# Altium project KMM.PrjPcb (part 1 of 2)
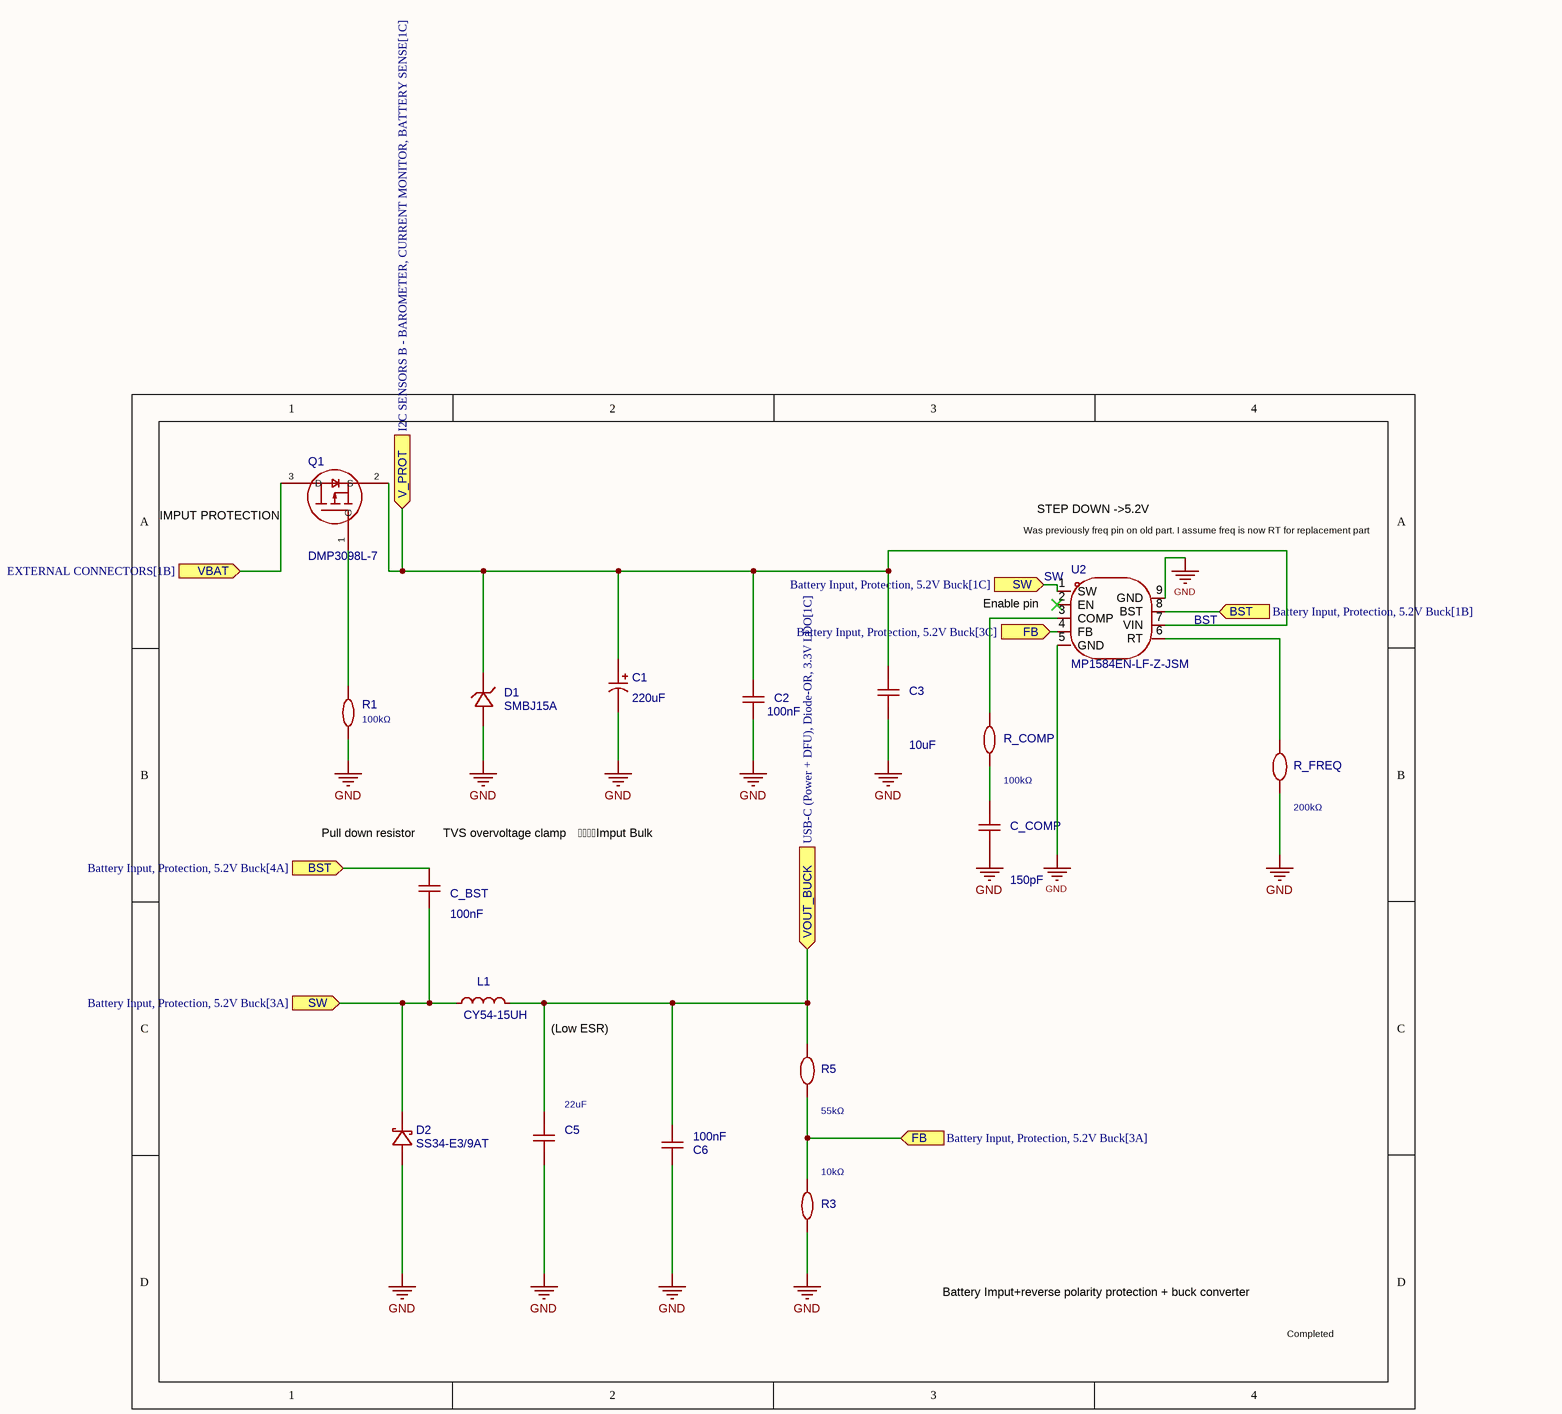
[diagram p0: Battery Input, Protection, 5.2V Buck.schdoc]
8 sheets, 81 parts. Net scope: flat (ports and power ports of the same name join across sheets).
Board file: PCB1.PcbDoc
Sheets:
  Battery Input, Protection, 5.2V Buck.schdoc
  EXTERNAL CONNECTORS.schdoc
  I2C Sensors A- IMU and Magnetometer.schdoc
  I2C SENSORS B - BAROMETER, CURRENT MONITOR, BATTERY SENSE.schdoc
  MCU Support Circuit.schdoc
  RC INPUT, STATUS LED, SWD HEADER.schdoc
  STM32F446RET6 Core.schdoc
  USB-C (Power + DFU), Diode-OR, 3.3V LDO.schdoc

## Sheet Battery Input, Protection, 5.2V Buck.schdoc
size 241 x 190 mm; Device: Altium_A; SheetNumber: 1; SheetTotal: 8; Name: Altium_A; Width: 950; Height: 750; X Region Count: 4; Y Region Count: 4; Blade Width: 20; Region Start: 1; Border: 1; Title Block Position: 3

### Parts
C1  220uF  [CAP-SMD_BD8.0-L8.3-W8.3-LS9.1-FD]
C2  100nF  [0603C]
C3  10uF  [0603C]
C5  22uF  [0603C]
C6  100nF  [0603C]
C_BST  100nF  [0603C]
C_COMP  150pF  [0603C]
D1  SMBJ15A  [SMB_L4.6-W3.5-LS5.3-RD]
D2  SS34-E3/9AT  [SMC-2_7r94x5r91-H2r34_C]
L1  CY54-15UH  [IND-SMD_L5.8-W5.2]
Q1  DMP3098L-7  [SOT-23_L2.9-W1.3-P1.90-LS2.4-BR]
R1  100kΩ  [0805R]
R3  10kΩ  [0805R]
R5  55kΩ  [0603R]
R_COMP  100kΩ  [0805R]
R_FREQ  200kΩ  [0603R]
U2  MP1584EN-LF-Z-JSM  [ESOP-8_L4.9-W3.9-P1.27-LS6.0-BL-EP-2]

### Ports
BST (in, see Battery Input, Protection, 5.2V Buck[1B]), BST (in, see Battery Input, Protection, 5.2V Buck[4A]), FB (in, see Battery Input, Protection, 5.2V Buck[3A]), FB (in, see Battery Input, Protection, 5.2V Buck[3C]), SW (in, see Battery Input, Protection, 5.2V Buck[1C]), SW (in, see Battery Input, Protection, 5.2V Buck[3A]), V_PROT (in, see I2C SENSORS B - BAROMETER, CURRENT MONITOR, BATTERY SENSE[1C]), VBAT (in, see EXTERNAL CONNECTORS[1B]), VOUT_BUCK (in, see USB-C (Power + DFU), Diode-OR, 3.3V LDO[1C])

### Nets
GND: C1.2 C2.2 C3.2 C5.2 C6.2 C_COMP.2 D1.2(A) D2.2(A) R1.2 R3.2 R_FREQ.2 U2.5(GND) U2.9(GND)
BST: C_BST.1 U2.8(BST) ; port BST
SW: C_BST.2 D2.1(K) L1.1 U2.1(SW) ; port SW
NetC1_1: C1.1 C2.1 C3.1 D1.1(C) Q1.2(S) U2.7(VIN) ; port V_PROT
NetC5_1: C5.1 C6.1 L1.2 R5.1 ; port VOUT_BUCK
NetC_COMP_1: C_COMP.1 R_COMP.2
NetJ_BAT_1: Q1.3(D) ; port VBAT
NetQ1_1: Q1.1(G) R1.1
NetR3_1: R3.1 R5.2 U2.4(FB) ; port FB
NetR_COMP_1: R_COMP.1 U2.3(COMP)
NetR_FREQ_1: R_FREQ.1 U2.6(RT)

Not connected (* = marked no-connect by the designer): U2 2(EN)*

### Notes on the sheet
- (near Q1) IMPUT PROTECTION
- Was previously freq pin on old part. I assume freq is now RT for replacement part
- STEP DOWN ->5.2V
- (near U2) Enable pin
- (near C_BST) Pull down resistor
- (near C_BST) TVS overvoltage clamp
- Imput Bulk
- (near L1) (Low ESR)
- Battery Imput+reverse polarity protection + buck converter
- Completed

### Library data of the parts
C1 = RVT1V221M0810 220UF 35V: Capacitance:220uF Tolerance:±20% Tolerance:±20% Voltage Rating:35V Ripple Current:195mA@120Hz Equivalent Series Resistance(ESR):- Diameter:8mm Height - Seated (Max):10.2mm Lifetime:2800hrs@105℃ Operating Temperature:-55℃~+105℃ Operating Temperature:-55℃~+; Manufacturer: DMBJ(振宝佳); Add into BOM: yes; Tolerance: ±20%; Voltage Rating: 35V; 3D Model: 9f9fc6857dc54a0ab164c419dde4584d; 3D Model Transform: 358.267,326.771,0,0,0,0,0,0,0
C2 C6 C_BST = CT41G-0603-2X1-50V-0.1uF-K(N): Capacitance:100nF Tolerance:±10% Tolerance:±10% Voltage Rating:50V Temperature Coefficient:-; Manufacturer: TORCH(火炬); Symbol: CT41G-0603-2X1-50V-0.1μF-K(N); Add into BOM: yes; Tolerance: ±10%; Voltage Rating: 50V; 3D Model: 624118aa3cc7497086c383c2d72e0852; 3D Model Transform: 62.992,31.496,0,0,0,0,0,0,0; ModelName: C0603_L1.6-W0.8-H0.8
C3 = 0603X106M250NT: Capacitance:10uF Tolerance:±20% Tolerance:±20% Voltage Rating:25V Temperature Coefficient:X5R; Manufacturer: FH(风华); Tolerance: ±20%; Voltage Rating: 25V; Add into BOM: yes; 3D Model: 624118aa3cc7497086c383c2d72e0852; 3D Model Transform: 62.992,31.496,0,0,0,0,0,0,0; Temperature Coefficient: X5R; ModelName: C0603_L1.6-W0.8-H0.8
C5 = CC0603MRX6S5BB226: Capacitance:22uF Tolerance:±20% Tolerance:±20% Voltage Rating:6.3V Temperature Coefficient:X6S; Manufacturer: YAGEO(国巨); Tolerance: ±20%; Voltage Rating: 6.3V; Add into BOM: yes; 3D Model: 624118aa3cc7497086c383c2d72e0852; 3D Model Transform: 62.992,31.496,0,0,0,0,0,0,0; Temperature Coefficient: X6S; ModelName: C0603_L1.6-W0.8-H0.8
C_COMP = CC0603CG50V151JN: Capacitance:150pF Tolerance:±5% Tolerance:±5% Voltage Rating:50V Temperature Coefficient:; Manufacturer: TORCH(火炬); Tolerance: ±5%; Voltage Rating: 50V; Add into BOM: yes; 3D Model: 624118aa3cc7497086c383c2d72e0852; 3D Model Transform: 62.992,31.496,0,0,0,0,0,0,0; ModelName: C0603_L1.6-W0.8-H0.8
D1 = SMBJ15A_C2912077: Polarity:Unidirectional Reverse Stand-Off Voltage (Vrwm):15V Clamping Voltage:24.4V Peak Pulse Current (Ipp):24.6A Peak Pulse Power Dissipation (Ppp):600W Voltage - Breakdown:18.5V Reverse Leakage Current (Ir):1uA Number of Channels:1 Operating Temperatur; Manufacturer: LRC(乐山无线电); Number of Channels: 1; Clamping Voltage: 24.4V; Add into BOM: yes; 3D Model: a9030ce42b7146a0b12fc063e3812f30; 3D Model Transform: 208.661,139.764,0,0,0,0,0,0,0; Reverse Stand-Off Voltage (Vrwm): 15V; Peak Pulse Current (Ipp): 24.6A; Peak Pulse Power Dissipation (Ppp): 600W; Voltage - Breakdown: 18.5V; Reverse Leakage Current (Ir): 1uA; Type: TVS
D2 = SS34-E3/9AT: Diode Configuration:1 Independent Voltage - Forward(Vf@If):500mV@3A Voltage - DC Reverse(Vr):40V Current - Rectified:3A Reverse Leakage Current (Ir):500uA@40V Operating Junction Temperature Range:-55℃~+150℃ Operating Junction Temperature Range:-55℃~+150℃; Manufacturer: VISHAY(威世); Add into BOM: yes; 3D Model: 181deed3e51b4528a83dd624c23bafda; 3D Model Transform: 314.96,236.22,0,0,0,0,0,0,0; Voltage - DC Reverse(Vr): 40V; Current - Rectified: 3A; Non-Repetitive Peak Forward Surge Current: 100A; ModelName: SMC_L6.9-W5.9-LS7.9-RD
L1 = CY54-15UH: Manufacturer: SHOU HAN(首韩); Add into BOM: yes; 3D Model: 65134515052944169492d54da43c5ebb; 3D Model Transform: 204.724,223.43,0,90,0,0,0,-0.018,0; ModelName: IND-SMD_L5.8-W5.2-H4.5
Q1 = DMP3098L-7: Number:1 P-Channel Drain to Source Voltage:30V Current - Continuous Drain(Id):3.8A RDS(on):120mΩ@4.5V Pd - Power Dissipation:1.08W Gate Threshold Voltage (Vgs(th)):2.1V Gate Charge(Qg):8nC@4.5V Input Capacitance(Ciss):336pF Reverse Transfer Capacitance (C; Manufacturer: DIODES(美台); Add into BOM: yes; 3D Model: 62a57c6760504a01965db6419a6d07df; 3D Model Transform: 98.64468,114.173,0,180,0,0,0.001,-0.002,0; Drain to Source Voltage: 30V; Current - Continuous Drain(Id): 3.8A; Pd - Power Dissipation: 1.08W; Gate Threshold Voltage (Vgs(th)): 2.1V; Input Capacitance(Ciss): 336pF; Reverse Transfer Capacitance (Crss@Vds): 147pF; Output Capacitance(Coss): 210pF; Vgs: ±20V; ModelName: SOT-23-3P_L2.9-W1.3-H1.0-LS2.4-P0.95
R1 = CR0805J80104G: Type:Thick Film Resistors Resistance: Tolerance:±5% Tolerance:±5% Power(Watts): Overload Voltage (Max): Temperature Coefficient:±200ppm/℃ Temperature Coefficient:±200ppm/℃ Operating Temperature Range:-55℃~+125℃ Operating Temperature Range:-55℃~+125℃; Manufacturer: LIZ(丽智电子); Add into BOM: yes; Tolerance: ±5%; 3D Model: b83c7c5430874b8eb2319a65d9433429; 3D Model Transform: 78.74,51.181,0,0,0,0,0,-0.0005,0; ModelName: R0805_L2.0-W1.3-H0.6
R3 = 0805W8F1002T5E: Type:Thick Film Resistor Resistance:10kΩ Tolerance:±1% Tolerance:±1% Power(Watts):125mW Voltage-Supply(Max):150V Temperature Coefficient:±100ppm/℃ Temperature Coefficient:±100ppm/℃ Operating Temperature:-55℃~+155℃ Operating Temperature:-55℃~+155℃; Manufacturer: UNI-ROYAL(厚声); Add into BOM: yes; Tolerance: ±1%; 3D Model: b83c7c5430874b8eb2319a65d9433429; 3D Model Transform: 78.74,51.181,0,0,0,0,0,-0.0005,0; Power(Watts): 125mW; Voltage-Supply(Max): 150V; ModelName: R0805_L2.0-W1.3-H0.6
R5 = CR165502F: Type:Thick Film Resistor Resistance:55kΩ Tolerance:±1% Tolerance:±1% Power(Watts):100mW Temperature Coefficient:±100ppm/℃ Temperature Coefficient:±100ppm/℃ Operating Temperature:-55℃~+155℃ Operating Temperature:-55℃~+155℃; Manufacturer: Meritek; Add into BOM: yes; Tolerance: ±1%; 3D Model: 112863783b5b41f1b5254f87eedc7932; 3D Model Transform: 31.8897,63.7794,0,90,0,0,0,0,0; Power(Watts): 100mW; ModelName: R0603
R_COMP = CR0805J80104G: Type:Thick Film Resistors Resistance: Tolerance:±5% Tolerance:±5% Power(Watts): Overload Voltage (Max): Temperature Coefficient:±200ppm/℃ Temperature Coefficient:±200ppm/℃ Operating Temperature Range:-55℃~+125℃ Operating Temperature Range:-55℃~+125℃; Manufacturer: LIZ(丽智电子); Tolerance: ±5%; Add into BOM: yes; 3D Model: b83c7c5430874b8eb2319a65d9433429; 3D Model Transform: 78.74,51.181,0,0,0,0,0,-0.0005,0; ModelName: R0805_L2.0-W1.3-H0.6
R_FREQ = FRC0603F2003TS: Type:Thick Film Resistor Resistance:200kΩ Tolerance:±1% Tolerance:±1% Power(Watts):100mW Voltage-Supply(Max):75V Temperature Coefficient:±100ppm/℃ Temperature Coefficient:±100ppm/℃ Operating Temperature:-55℃~+155℃ Operating Temperature:-55℃~+155℃; Manufacturer: FOJAN(富捷); Add into BOM: yes; Tolerance: ±1%; 3D Model: 112863783b5b41f1b5254f87eedc7932; 3D Model Transform: 31.8897,63.7794,0,90,0,0,0,0,0; Power(Watts): 100mW; Voltage-Supply(Max): 75V; ModelName: R0603
U2 = MP1584EN-LF-Z-JSM: Function:Step-down type Voltage - Supply:4.5V~40V Voltage - Supply:4.5V~40V Output Voltage:800mV~37V Output Voltage:800mV~37V Output Current:3A Frequency - Switching:100kHz~220kHz Frequency - Switching:100kHz~220kHz Operating Temperature:-40℃~+125℃ Operat; Manufacturer: JSMSEMI(杰盛微); Output Type: Adjustable; Output Current: 3A; Add into BOM: yes; 3D Model: e5df7a25454141cab5fb3454c06ecccd; 3D Model Transform: 192.913,236.22,0,0,0,0,0,0,0; Synchronous Rectifier: No; Number of Outputs: 1; Topology: Buck; Quiescent Current: 65uA; Switch tube (built-in/external): Built-in

## Sheet EXTERNAL CONNECTORS.schdoc
size 241 x 190 mm; Device: Altium_A; SheetNumber: 2; SheetTotal: 8; Name: Altium_A; Width: 950; Height: 750; X Region Count: 4; Y Region Count: 4; Blade Width: 20; Region Start: 1; Border: 1; Title Block Position: 3
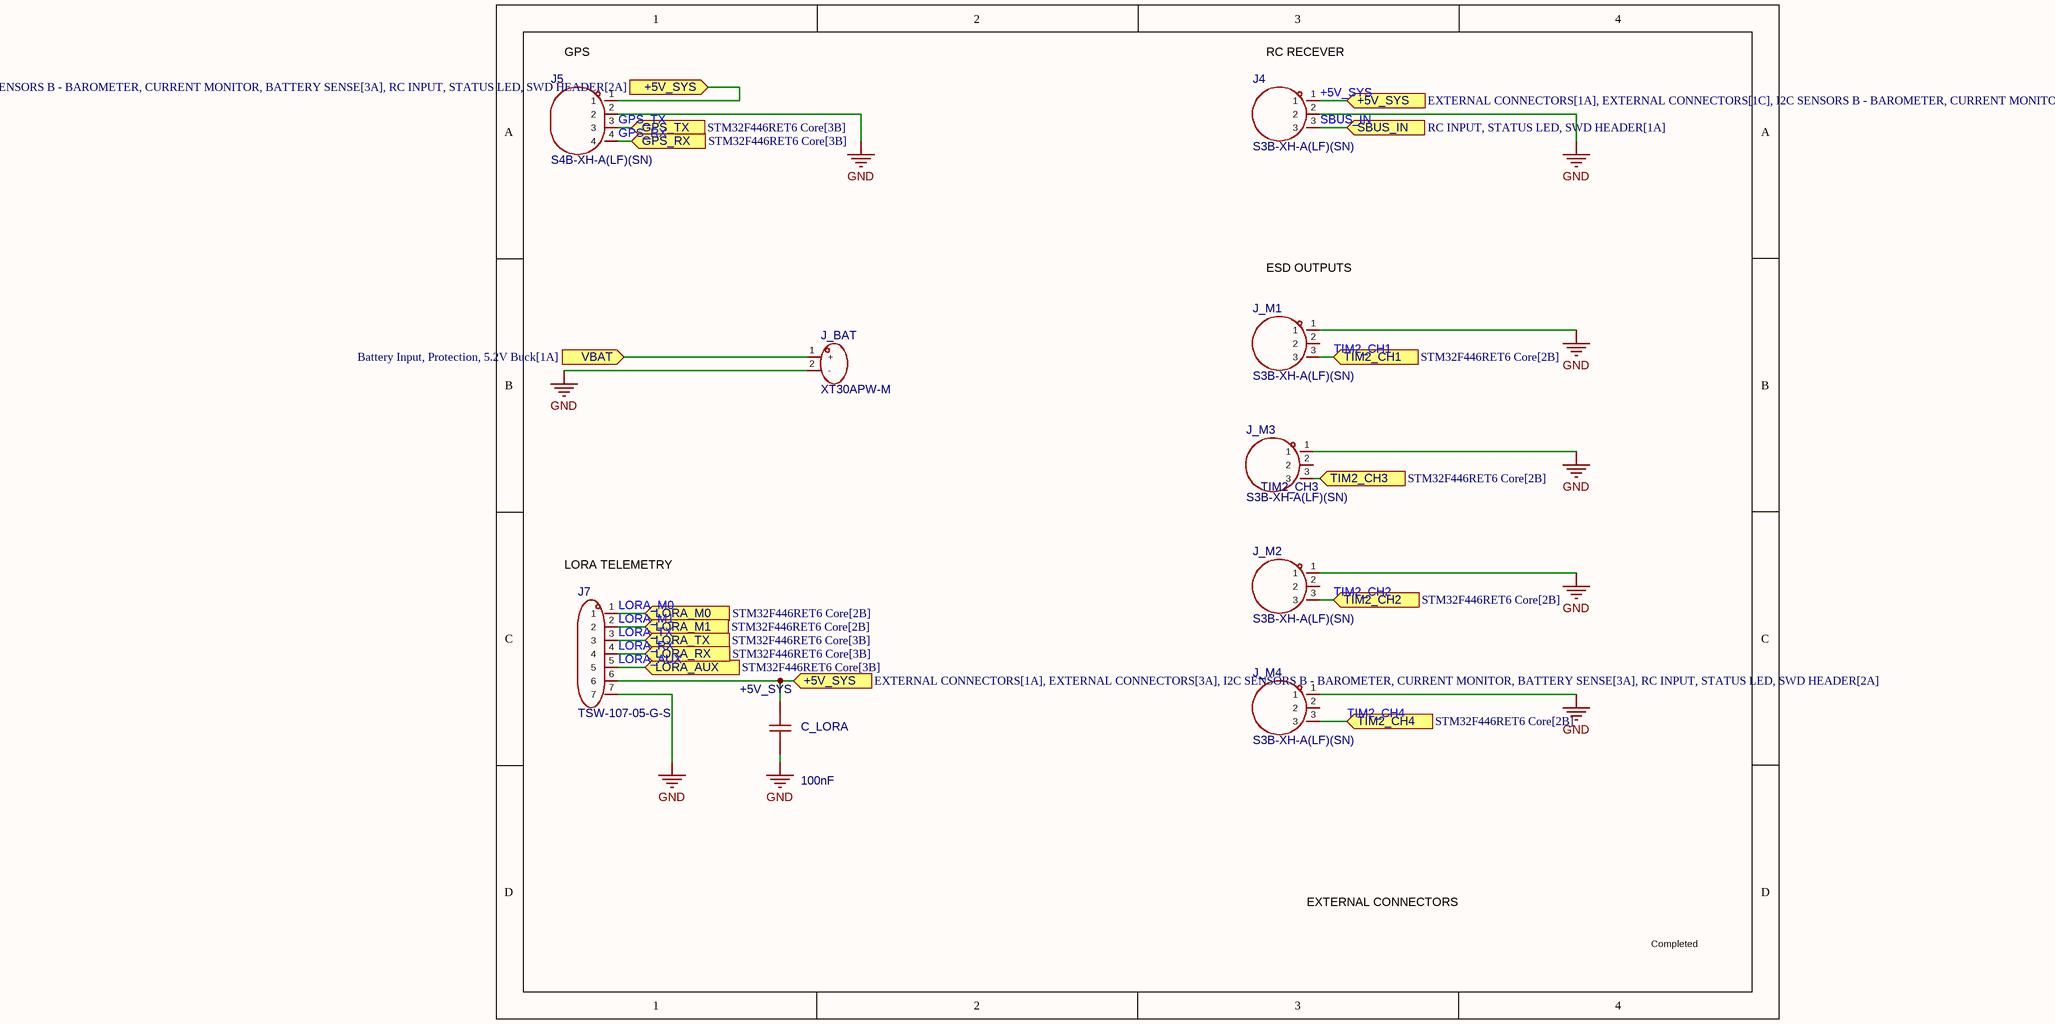
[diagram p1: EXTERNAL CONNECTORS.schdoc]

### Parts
C_LORA  100nF  [0603C]
J4  S3B-XH-A(LF)(SN)  [CONN-TH_S3B-XH-A-LF-SN]
J5  S4B-XH-A(LF)(SN)  [CONN-TH_S4B-XH-A-LF-SN]
J7  TSW-107-05-G-S  [HDR-TH_7P-P2.54-V-M]
J_BAT  XT30APW-M  [CONN-TH_XT30APW-M]
J_M1  S3B-XH-A(LF)(SN)  [CONN-TH_S3B-XH-A-LF-SN]
J_M2  S3B-XH-A(LF)(SN)  [CONN-TH_S3B-XH-A-LF-SN]
J_M3  S3B-XH-A(LF)(SN)  [CONN-TH_S3B-XH-A-LF-SN]
J_M4  S3B-XH-A(LF)(SN)  [CONN-TH_S3B-XH-A-LF-SN]

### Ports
+5V_SYS (in, see EXTERNAL CONNECTORS[1A], EXTERNAL CONNECTORS[1C], I2C SENSORS B - BAROMETER, CURRENT MONITOR, BATTERY SENSE[3A], RC INPUT, STATUS LED, SWD HEADER[2A]), +5V_SYS (in, see EXTERNAL CONNECTORS[1A], EXTERNAL CONNECTORS[3A], I2C SENSORS B - BAROMETER, CURRENT MONITOR, BATTERY SENSE[3A], RC INPUT, STATUS LED, SWD HEADER[2A]), +5V_SYS (in, see EXTERNAL CONNECTORS[1C], EXTERNAL CONNECTORS[3A], I2C SENSORS B - BAROMETER, CURRENT MONITOR, BATTERY SENSE[3A], RC INPUT, STATUS LED, SWD HEADER[2A]), GPS_RX (in, see STM32F446RET6 Core[3B]), GPS_TX (in, see STM32F446RET6 Core[3B]), LORA_AUX (in, see STM32F446RET6 Core[3B]), LORA_M0 (in, see STM32F446RET6 Core[2B]), LORA_M1 (in, see STM32F446RET6 Core[2B]), LORA_RX (in, see STM32F446RET6 Core[3B]), LORA_TX (in, see STM32F446RET6 Core[3B]), SBUS_IN (in, see RC INPUT, STATUS LED, SWD HEADER[1A]), TIM2_CH1 (in, see STM32F446RET6 Core[2B]), TIM2_CH2 (in, see STM32F446RET6 Core[2B]), TIM2_CH3 (in, see STM32F446RET6 Core[2B]), TIM2_CH4 (in, see STM32F446RET6 Core[2B]), VBAT (in, see Battery Input, Protection, 5.2V Buck[1A])

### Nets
GND: C_LORA.2 J4.2 J5.2 J7.7 J_BAT.2(-) J_M1.1 J_M2.1 J_M3.1 J_M4.1
+5V_SYS: C_LORA.1 J4.1 J5.1 J7.6 ; port +5V_SYS
GPS_RX: J5.4 ; port GPS_RX
GPS_TX: J5.3 ; port GPS_TX
LORA_AUX: J7.5 ; port LORA_AUX
LORA_M0: J7.1 ; port LORA_M0
LORA_M1: J7.2 ; port LORA_M1
LORA_RX: J7.4 ; port LORA_RX
LORA_TX: J7.3 ; port LORA_TX
SBUS_IN: J4.3 ; port SBUS_IN
TIM2_CH1: J_M1.3 ; port TIM2_CH1
TIM2_CH2: J_M2.3 ; port TIM2_CH2
TIM2_CH3: J_M3.3 ; port TIM2_CH3
TIM2_CH4: J_M4.3 ; port TIM2_CH4
NetJ_BAT_1: J_BAT.1(+) ; port VBAT

Not connected (* = marked no-connect by the designer): J_M1 2; J_M2 2; J_M3 2; J_M4 2

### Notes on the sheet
- (near J5) GPS
- (near J4) RC RECEVER
- ESD OUTPUTS
- (near J7) LORA TELEMETRY
- EXTERNAL CONNECTORS
- Completed

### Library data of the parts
C_LORA = 06035C104K4T2A: Capacitance:100nF Tolerance:±10% Tolerance:±10% Voltage Rating:50V Temperature Coefficient:X7R; Manufacturer: Kyocera AVX; Add into BOM: yes; Tolerance: ±10%; Voltage Rating: 50V; 3D Model: 624118aa3cc7497086c383c2d72e0852; 3D Model Transform: 62.992,31.496,0,0,0,0,0,0,0; Temperature Coefficient: X7R; ModelName: C0603_L1.6-W0.8-H0.8
J4 J_M1-J_M4 = S3B-XH-A(LF)(SN): Pins Structure:1x3P Pitch:2.5mm Mounting Style:Bend insert Reference Series:XH Number of Pins:3P Number of Rows:1 Number of PINs Per Row:3 Row Spacing:- Current Rating (Max):3A Contact Material:Brass Contact Plating:Tin Operating Temperature Range:-25℃~+8; Manufacturer: JST; Add into BOM: yes; 3D Model: 53e830ec92554ce8b6ebb98afce921f9; 3D Model Transform: 389.763,452.755,0,0,0,0,0,136.378,-137.795; Pins Structure: 1x3P; Pitch: 2.5mm; Reference Series: XH; Number of PINs Per Row: 3; Current Rating (Max): 3A; Rated Voltage (Max): 250V; Plastic Material: PA66; Flame Retardant Rating: UL94V-0; Supplementary Features: K-leg punch; Z-Height of the Board: 6.1mm; X-Length of Bottom Edge on Board (Spacing Line): 9.9mm; Y-Width of Bottom Edge on Board: 11.5mm
J5 = S4B-XH-A(LF)(SN): Pins Structure:1x4P Pitch:2.5mm Mounting Type:Right Angle Reference Series:XH Number of Pins:4P Number of Rows:1 Number of PINs Per Row:4 Row Spacing:- Current Rating:3A Contact Material:Brass Contact Plating:Tin Operating Temperature:-25℃~+85℃ Operating; Manufacturer: JST; Add into BOM: yes; Voltage Rating: 250V; 3D Model: 77a2ced4cba941c49e3f4130b9ad2f4f; 3D Model Transform: 488.19194,452.755,0,180,0,0,0.591,136.378,-133.858; Pins Structure: 1x4P; Pitch: 2.5mm; Reference Series: XH; Number of PINs Per Row: 4; Current Rating: 3A; Plastic Material: PA66; Flame Retardant Rating: UL94V-0; Supplementary Features: K Pin; Z-Height of the Board: 6.1mm; X-Length of Bottom Edge on Board (Spacing Line): 12.4mm; Y-Width of Bottom Edge on Board: 11.5mm
J7 = TSW-107-05-G-S: Pitch:2.54mm Mounting Type:Through Hole Number of Rows:1 Number of Pins:7P Contact Material:Phosphor Bronze Contact Plating:Gold Operating Temperature:-55℃~+125℃ Operating Temperature:-55℃~+125℃ Color:Black; Manufacturer: SAMTEC; Add into BOM: yes; Pitch: 2.54mm; 3D Model: ce62eac80ffd4cbe92d29651b85d1296; 3D Model Transform: 690.1561,98.425,0,0,0,0,0,0,-118.11; ModelName: HDR-TH_7P-P2.54-M-LI-1X7P
J_BAT = XT30APW-M: Manufacturer: AMASS(艾迈斯); Add into BOM: yes; 3D Model: 34352084f5c04524b23500f5e8e2b035; 3D Model Transform: 390.1567,511.81,0,0,0,0,-0.005,220.472,-118.11

## Sheet I2C Sensors A- IMU and Magnetometer.schdoc
size 241 x 190 mm; Device: Altium_A; SheetNumber: 3; SheetTotal: 8; Name: Altium_A; Width: 950; Height: 750; X Region Count: 4; Y Region Count: 4; Blade Width: 20; Region Start: 1; Border: 1; Title Block Position: 3
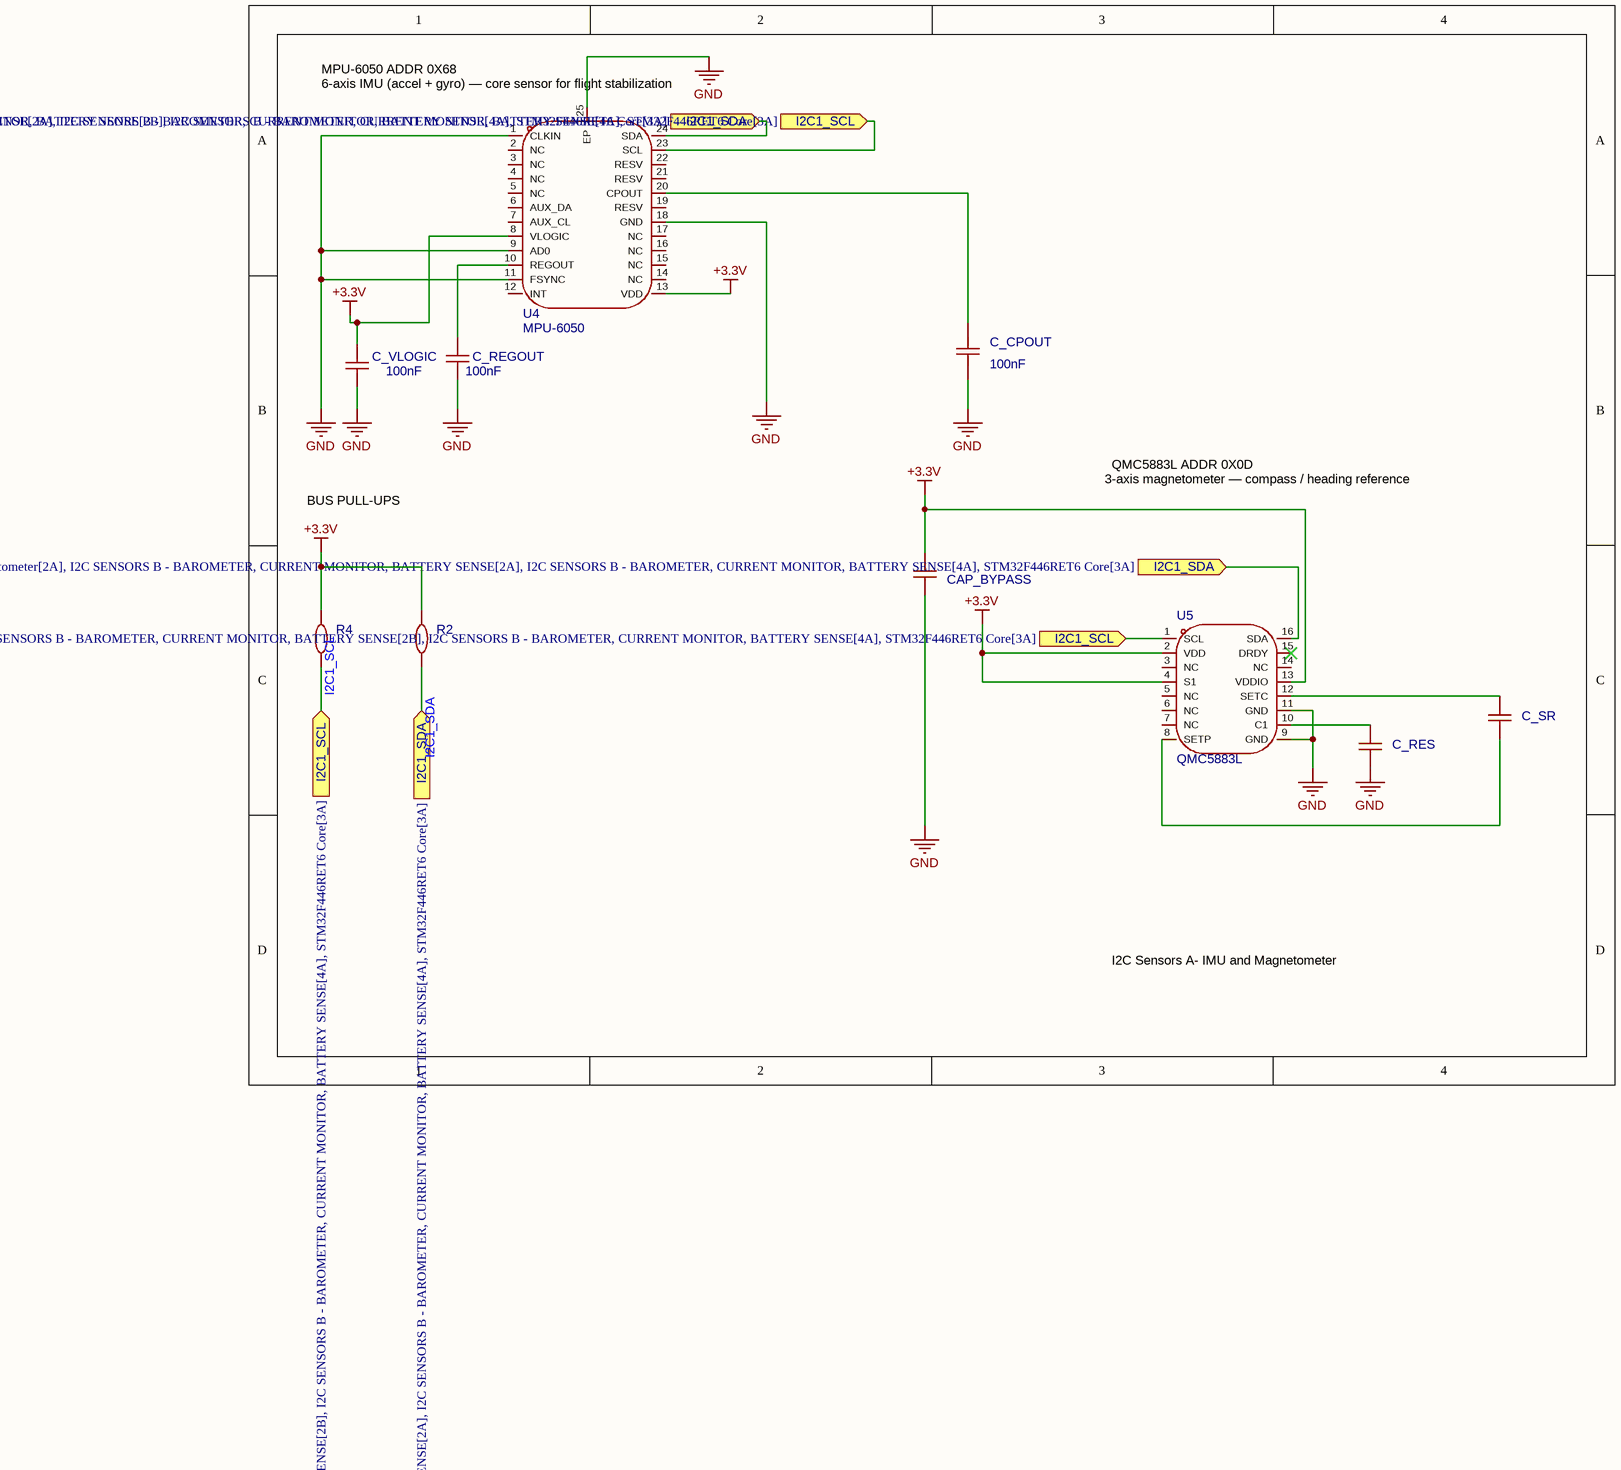
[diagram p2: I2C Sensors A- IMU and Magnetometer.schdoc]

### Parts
C_CPOUT  100nF  [0603C]
C_REGOUT  100nF  [0603C]
C_RES  100nF  [0603C]  (value not drawn)
C_SR  100nF  [0603C]  (value not drawn)
C_VLOGIC  100nF  [0603C]
CAP_BYPASS  100nF  [0603C]  (value not drawn)
R2  2.2kΩ  [0603R]  (value not drawn)
R4  2kΩ  [0603R]  (value not drawn)
U4  MPU-6050  [QFN-24_L4.0-W4.0-P0.50-BL-EP2.7]
U5  QMC5883L  [LGA-16_L3.0-W3.0-P0.50-TL]

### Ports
I2C1_SCL (in, see I2C Sensors A- IMU and Magnetometer[1C], I2C Sensors A- IMU and Magnetometer[2A], I2C SENSORS B - BAROMETER, CURRENT MONITOR, BATTERY SENSE[2B], I2C SENSORS B - BAROMETER, CURRENT MONITOR, BATTERY SENSE[4A], STM32F446RET6 Core[3A]), I2C1_SCL (in, see I2C Sensors A- IMU and Magnetometer[1C], I2C Sensors A- IMU and Magnetometer[3C], I2C SENSORS B - BAROMETER, CURRENT MONITOR, BATTERY SENSE[2B], I2C SENSORS B - BAROMETER, CURRENT MONITOR, BATTERY SENSE[4A], STM32F446RET6 Core[3A]), I2C1_SCL (in, see I2C Sensors A- IMU and Magnetometer[2A], I2C Sensors A- IMU and Magnetometer[3C], I2C SENSORS B - BAROMETER, CURRENT MONITOR, BATTERY SENSE[2B], I2C SENSORS B - BAROMETER, CURRENT MONITOR, BATTERY SENSE[4A], STM32F446RET6 Core[3A]), I2C1_SDA (in, see I2C Sensors A- IMU and Magnetometer[1C], I2C Sensors A- IMU and Magnetometer[2A], I2C SENSORS B - BAROMETER, CURRENT MONITOR, BATTERY SENSE[2A], I2C SENSORS B - BAROMETER, CURRENT MONITOR, BATTERY SENSE[4A], STM32F446RET6 Core[3A]), I2C1_SDA (in, see I2C Sensors A- IMU and Magnetometer[1C], I2C Sensors A- IMU and Magnetometer[3C], I2C SENSORS B - BAROMETER, CURRENT MONITOR, BATTERY SENSE[2A], I2C SENSORS B - BAROMETER, CURRENT MONITOR, BATTERY SENSE[4A], STM32F446RET6 Core[3A]), I2C1_SDA (in, see I2C Sensors A- IMU and Magnetometer[2A], I2C Sensors A- IMU and Magnetometer[3C], I2C SENSORS B - BAROMETER, CURRENT MONITOR, BATTERY SENSE[2A], I2C SENSORS B - BAROMETER, CURRENT MONITOR, BATTERY SENSE[4A], STM32F446RET6 Core[3A])

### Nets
+3.3V: C_VLOGIC.1 CAP_BYPASS.1 R2.1 R4.1 U4.8(VLOGIC) U4.13(VDD) U5.2(VDD) U5.4(S1) U5.13(VDDIO)
GND: C_CPOUT.1 C_REGOUT.2 C_RES.2 C_VLOGIC.2 CAP_BYPASS.2 U4.1(CLKIN) U4.9(AD0) U4.11(FSYNC) U4.18(GND) U4.25(EP) U5.9(GND) U5.11(GND)
I2C1_SCL: R4.2 U4.23(SCL) U5.1(SCL) ; port I2C1_SCL
I2C1_SDA: R2.2 U4.24(SDA) U5.16(SDA) ; port I2C1_SDA
NetC_CPOUT_2: C_CPOUT.2 U4.20(CPOUT)
NetC_REGOUT_1: C_REGOUT.1 U4.10(REGOUT)
NetC_RES_1: C_RES.1 U5.10(C1)
NetC_SR_1: C_SR.1 U5.12(SETC)
NetC_SR_2: C_SR.2 U5.8(SETP)

Not connected (* = marked no-connect by the designer): U4 2(NC) 3(NC) 4(NC) 5(NC) 6(AUX_DA) 7(AUX_CL) 12(INT) 14(NC) 15(NC) 16(NC) 17(NC) 19(RESV) 21(RESV) 22(RESV); U5 3(NC) 5(NC) 6(NC) 7(NC) 14(NC) 15(DRDY)*

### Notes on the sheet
- MPU-6050 ADDR 0X68
- (near U4) 6-axis IMU (accel + gyro) — core sensor for flight stabilization
- QMC5883L ADDR 0X0D
- BUS PULL-UPS
- 3-axis magnetometer — compass / heading reference
- I2C Sensors A- IMU and Magnetometer

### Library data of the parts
C_CPOUT = 0603B104K500CT: Capacitance: Tolerance:±10% Tolerance:±10% Voltage Rated: Temperature Coefficient:; Manufacturer: Walsin(华新科); Tolerance: ±10%; Symbol: 0603B104K500CT_C314282; Add into BOM: yes; 3D Model: 624118aa3cc7497086c383c2d72e0852; 3D Model Transform: 62.992,31.496,0,0,0,0,0,0,0; ModelName: C0603_L1.6-W0.8-H0.8
C_REGOUT C_RES C_SR C_VLOGIC CAP_BYPASS = CT41G-0603-2X1-50V-0.1uF-K(N): Capacitance:100nF Tolerance:±10% Tolerance:±10% Voltage Rating:50V Temperature Coefficient:-; Manufacturer: TORCH(火炬); Tolerance: ±10%; Voltage Rating: 50V; Symbol: CT41G-0603-2X1-50V-0.1μF-K(N); Add into BOM: yes; 3D Model: 624118aa3cc7497086c383c2d72e0852; 3D Model Transform: 62.992,31.496,0,0,0,0,0,0,0; ModelName: C0603_L1.6-W0.8-H0.8
R2 = RMC06032.2K5%N: Type:Thick Film Resistor Resistance:2.2kΩ Tolerance:±5% Tolerance:±5% Power(Watts):100mW Voltage-Supply(Max):50V Temperature Coefficient:±100ppm/℃ Temperature Coefficient:±100ppm/℃ Operating Temperature:-55℃~+155℃ Operating Temperature:-55℃~+155℃; Manufacturer: Tyohm(幸亚电阻); Add into BOM: yes; Tolerance: ±5%; 3D Model: 112863783b5b41f1b5254f87eedc7932; 3D Model Transform: 31.8897,63.7794,0,90,0,0,0,0,0; Power(Watts): 100mW; Voltage-Supply(Max): 50V; ModelName: R0603
R4 = 0603WAF2001T5E: Type:Thick Film Resistor Resistance:2kΩ Tolerance:±1% Tolerance:±1% Power(Watts):100mW Voltage-Supply(Max):75V Temperature Coefficient:±100ppm/℃ Temperature Coefficient:±100ppm/℃ Operating Temperature:-55℃~+155℃ Operating Temperature:-55℃~+155℃; Manufacturer: UNI-ROYAL(厚声); Add into BOM: yes; Tolerance: ±1%; 3D Model: 112863783b5b41f1b5254f87eedc7932; 3D Model Transform: 31.8897,63.7794,0,90,0,0,0,0,0; Power(Watts): 100mW; Voltage-Supply(Max): 75V; ModelName: R0603
U4 = MPU-6050: Accelerometer Sensing Axis:X,Y,Z Acceleration Measurement Range (MAX):±16g Acceleration Measurement Range (MAX):±16g Gyroscope Sensing Axis:X,Y,Z Gyroscope Measurement Range (MAX):±2000dps Gyroscope Measurement Range (MAX):±2000dps Sensor Type:IMU (accele; Manufacturer: TDK InvenSense(应美盛); Sensor Type: IMU (accelerometer + gyroscope); Symbol: MPU-6050_C24112; Add into BOM: yes; 3D Model: 44c25c28ff7644d2af30aa63ffb9dd1f; 3D Model Transform: 158.267,158.267,0,0,0,0,0,0,0; Accelerometer Sensing Axis: X,Y,Z; Acceleration Measurement Range (MAX): ±16g; Output Bits: 16bit; Interface: I2C; Voltage - Supply: 2.375V~3.46V; Cache Size: 1KB; Standby Current: 5uA
U5 = QMC5883L: Magnetic Sensing Range(X,Y):±8Gs Magnetic Sensing Range(X,Y):±8Gs Magnetic Sensing Range(Z):±8Gs Magnetic Sensing Range(Z):±8Gs Output bit:16bit Interface Type:I2C Voltage - Supply:2.16V~3.6V Voltage - Supply:2.16V~3.6V Current - Supply:75uA Operating Tem; Manufacturer: QST(上海矽睿); Add into BOM: yes; 3D Model: 82d0b24f8ce34137af889e86d6d49db7; 3D Model Transform: 118.11,118.11,0,90,0,0,0,0,0; Magnetic Sensing Range(X,Y): ±8Gs; Output bit: 16bit; Interface Type: I2C; Current - Supply: 75uA; ModelName: LGA-16_L3.0-W3.0-H0.9-P0.50

## Sheet I2C SENSORS B - BAROMETER, CURRENT MONITOR, BATTERY SENSE.schdoc
size 241 x 190 mm; Device: Altium_A; SheetNumber: 4; SheetTotal: 8; Name: Altium_A; Width: 950; Height: 750; X Region Count: 4; Y Region Count: 4; Blade Width: 20; Region Start: 1; Border: 1; Title Block Position: 3
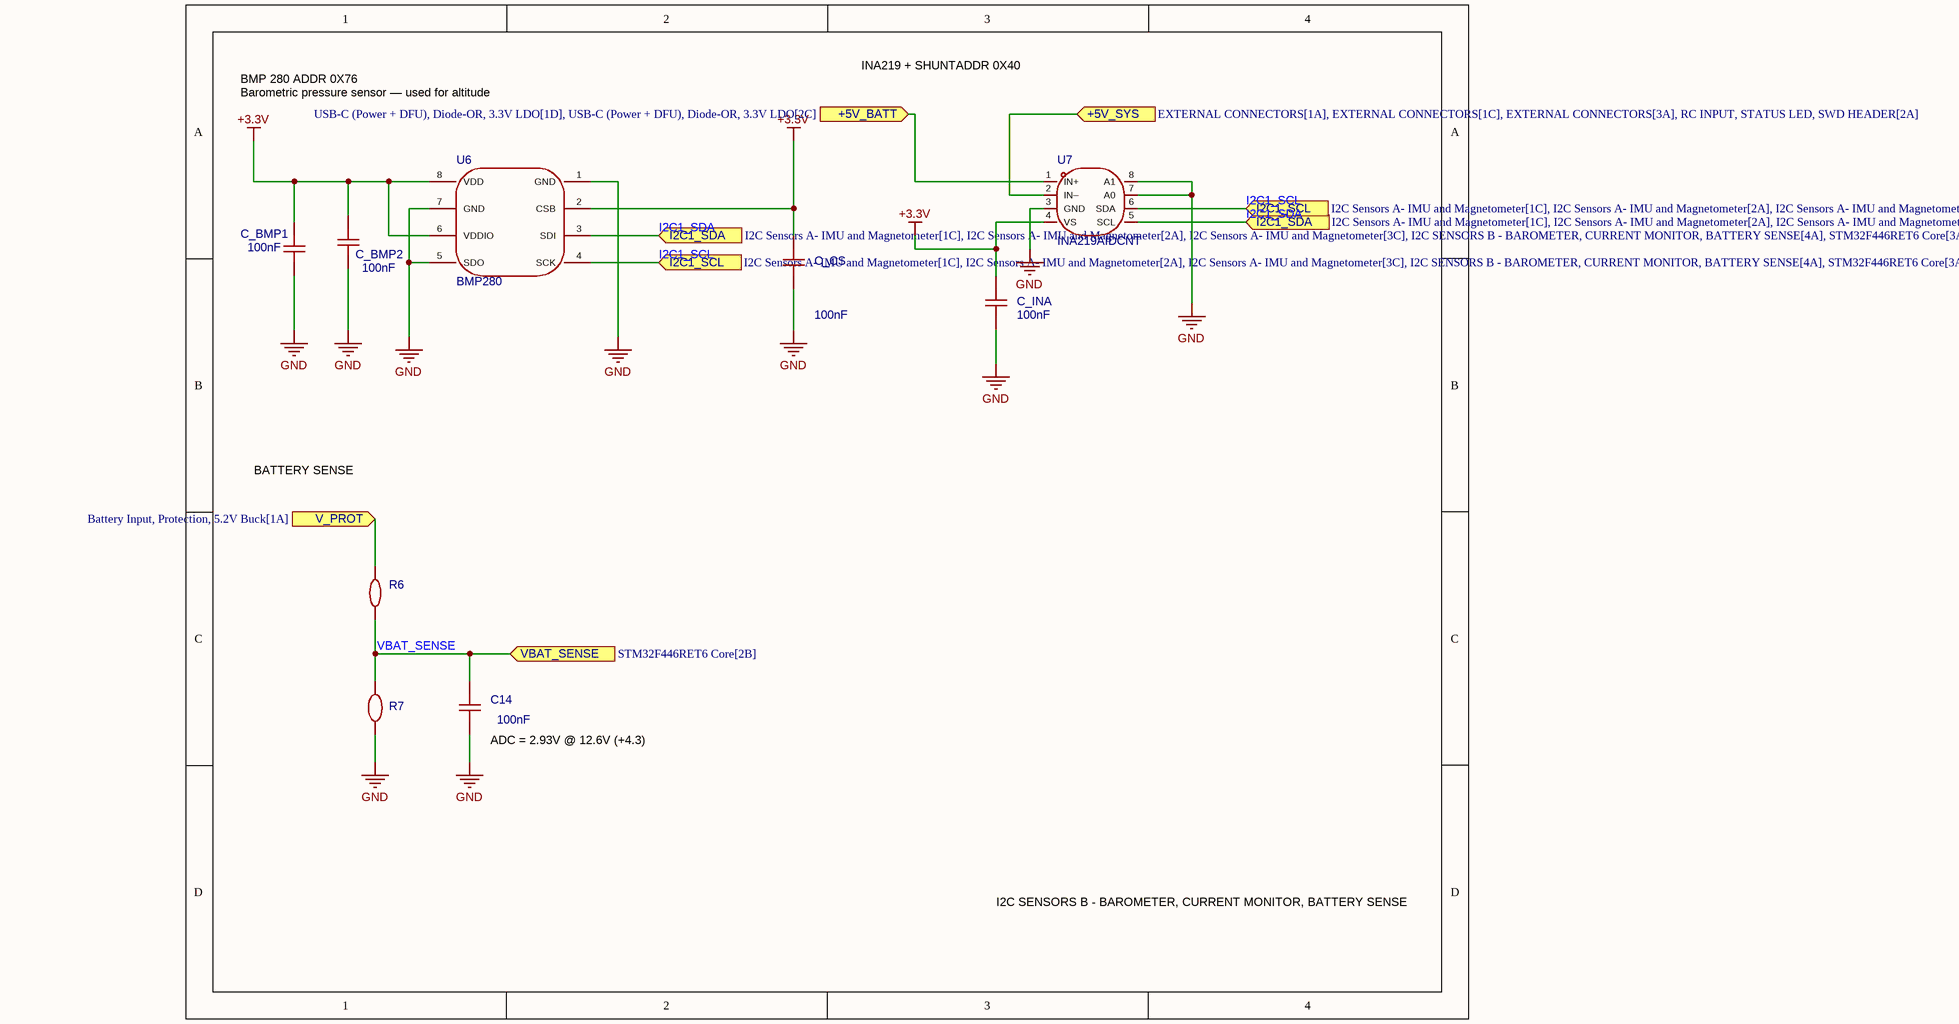
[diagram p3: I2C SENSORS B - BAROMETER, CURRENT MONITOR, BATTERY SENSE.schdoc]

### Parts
C14  100nF  [1206C]
C_BMP1  100nF  [1206C]
C_BMP2  100nF  [1206C]
C_CS  100nF  [1206C]
C_INA  100nF  [1206C]
R6  3kΩ  [0603R]  (value not drawn)
R7  10kΩ  [0603R]  (value not drawn)
U6  BMP280  [SENSOR-TH_BMP280-BL]
U7  INA219AIDCNT  [SOT-23-8_L2.9-W1.6-P0.65-LS2.8-BR]

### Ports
+5V_BATT (in, see USB-C (Power + DFU), Diode-OR, 3.3V LDO[1D], USB-C (Power + DFU), Diode-OR, 3.3V LDO[2C]), +5V_SYS (in, see EXTERNAL CONNECTORS[1A], EXTERNAL CONNECTORS[1C], EXTERNAL CONNECTORS[3A], RC INPUT, STATUS LED, SWD HEADER[2A]), I2C1_SCL (in, see I2C Sensors A- IMU and Magnetometer[1C], I2C Sensors A- IMU and Magnetometer[2A], I2C Sensors A- IMU and Magnetometer[3C], I2C SENSORS B - BAROMETER, CURRENT MONITOR, BATTERY SENSE[2B], STM32F446RET6 Core[3A]), I2C1_SCL (in, see I2C Sensors A- IMU and Magnetometer[1C], I2C Sensors A- IMU and Magnetometer[2A], I2C Sensors A- IMU and Magnetometer[3C], I2C SENSORS B - BAROMETER, CURRENT MONITOR, BATTERY SENSE[4A], STM32F446RET6 Core[3A]), I2C1_SDA (in, see I2C Sensors A- IMU and Magnetometer[1C], I2C Sensors A- IMU and Magnetometer[2A], I2C Sensors A- IMU and Magnetometer[3C], I2C SENSORS B - BAROMETER, CURRENT MONITOR, BATTERY SENSE[2A], STM32F446RET6 Core[3A]), I2C1_SDA (in, see I2C Sensors A- IMU and Magnetometer[1C], I2C Sensors A- IMU and Magnetometer[2A], I2C Sensors A- IMU and Magnetometer[3C], I2C SENSORS B - BAROMETER, CURRENT MONITOR, BATTERY SENSE[4A], STM32F446RET6 Core[3A]), V_PROT (in, see Battery Input, Protection, 5.2V Buck[1A]), VBAT_SENSE (in, see STM32F446RET6 Core[2B])

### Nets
+3.3V: C_BMP1.1 C_BMP2.1 C_CS.1 C_INA.1 U6.2(CSB) U6.6(VDDIO) U6.8(VDD) U7.4(VS)
GND: C14.2 C_BMP1.2 C_BMP2.2 C_CS.2 C_INA.2 R7.2 U6.1(GND) U6.5(SDO) U6.7(GND) U7.3(GND) U7.7(A0) U7.8(A1)
+5V_SYS: U7.2(IN–) ; port +5V_SYS
I2C1_SCL: U6.4(SCK) U7.6(SDA) ; port I2C1_SCL
I2C1_SDA: U6.3(SDI) U7.5(SCL) ; port I2C1_SDA
VBAT_SENSE: C14.1 R6.2 R7.1 ; port VBAT_SENSE
NetC1_1: R6.1 ; port V_PROT
NetC_LDO_IN_1: U7.1(IN+) ; port +5V_BATT

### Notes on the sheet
- BMP 280 ADDR 0X76
- Barometric pressure sensor — used for altitude
- INA219 + SHUNTADDR 0X40
- BATTERY SENSE
- (near C14) ADC = 2.93V @ 12.6V (+4.3)
- I2C SENSORS B - BAROMETER, CURRENT MONITOR, BATTERY SENSE

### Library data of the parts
C14 C_BMP1 C_BMP2 C_INA = CGA1206M3L104J101MT: Capacitance:100nF Tolerance:±5% Tolerance:±5% Voltage Rating:100V Temperature Coefficient:-; Manufacturer: HRE(芯声); Tolerance: ±5%; Voltage Rating: 100V; Add into BOM: yes; 3D Model: c6790e9475e1483991d2c64340b24e96; 3D Model Transform: 125.984,62.992,0,0,0,0,0,0,0; ModelName: C1206_L3.2-W1.6-H1.3
C_CS = CGA1206M3L104J101MT: Capacitance:100nF Tolerance:±5% Tolerance:±5% Voltage Rating:100V Temperature Coefficient:-; Manufacturer: HRE(芯声); Add into BOM: yes; Tolerance: ±5%; Voltage Rating: 100V; 3D Model: c6790e9475e1483991d2c64340b24e96; 3D Model Transform: 125.984,62.992,0,0,0,0,0,0,0; ModelName: C1206_L3.2-W1.6-H1.3
R6 = RMC06033K5%N: Type:Thick Film Resistor Resistance:3kΩ Tolerance:±5% Tolerance:±5% Power(Watts):100mW Voltage-Supply(Max):50V Temperature Coefficient:±100ppm/℃ Temperature Coefficient:±100ppm/℃ Operating Temperature:-55℃~+155℃ Operating Temperature:-55℃~+155℃; Manufacturer: Tyohm(幸亚电阻); Add into BOM: yes; Tolerance: ±5%; 3D Model: 112863783b5b41f1b5254f87eedc7932; 3D Model Transform: 31.8897,63.7794,0,90,0,0,0,0,0; Power(Watts): 100mW; Voltage-Supply(Max): 50V; ModelName: R0603
R7 = PTFR0603Q10K0N9: Type:Thin Film Resistor Resistance:10kΩ Tolerance:±0.02% Tolerance:±0.02% Power(Watts):100mW Voltage-Supply(Max):100V Temperature Coefficient:±10ppm/℃ Temperature Coefficient:±10ppm/℃ Operating Temperature:-55℃~+155℃ Operating Temperature:-55℃~+155℃; Manufacturer: RESI(开步睿思); Add into BOM: yes; Tolerance: ±0.02%; 3D Model: 112863783b5b41f1b5254f87eedc7932; 3D Model Transform: 31.8897,63.7794,0,90,0,0,0,0,0; Power(Watts): 100mW; Voltage-Supply(Max): 100V; ModelName: R0603
U6 = BMP280: Pressure range:30Kpa~1.1bar Pressure range:30Kpa~1.1bar Voltage - Supply:1.71V~3.6V Voltage - Supply:1.71V~3.6V Standby Current:300nA Interface:SPI；I2C Module:- Absolute Accuracy:1hpa Relative Accuracy:0.12hpa Features:Standby mode；Integrated ADC and digi; Manufacturer: Bosch(博世); Add into BOM: yes; 3D Model: c4abf9833e0a46728e057941439f0c97; 3D Model Transform: 78.74,98.425,0,0,0,0,0,0,0; Standby Current: 300nA; Absolute Accuracy: 1hpa; Temperature Coefficient of Offset(TCO): 1.5pa/K; ModelName: LGA-8_L2.5-W2.0-P0.65_AMP6127
U7 = INA219AIDCNT: Number of Channels:- Vcm - Common Mode Voltage:0V~26V Vcm - Common Mode Voltage:0V~26V Gain:- Bandwidth:- Ib - Input Bias Current:20nA Vos - Input Offset Voltage:10uV Operating Temperature:-40℃~+125℃ Operating Temperature:-40℃~+125℃ Differential Voltage:±; Manufacturer: TI(德州仪器); Add into BOM: yes; 3D Model: 16ef541b161f401ca0ff6f17d80abb5e; 3D Model Transform: 110.73,114.173,0,180,0,0,0,-0.0005,0; Vcm - Common Mode Voltage: 0V~26V; Ib - Input Bias Current: 20nA; Vos - Input Offset Voltage: 10uV; Differential Voltage: ±26V; Single Supply: 3V~5.5V; Quiescent Current: 700uA; Input Offset Voltage Drift(Vos TC): 0.1uV/℃; Common Mode Rejection Ratio (CMRR): 120dB; ModelName: SOT-23-8_L2.9-W1.6-H1.5-LS2.8-P0.65

## Sheet MCU Support Circuit.schdoc
size 241 x 190 mm; Device: Altium_A; SheetNumber: 5; SheetTotal: 8; Name: Altium_A; Width: 950; Height: 750; X Region Count: 4; Y Region Count: 4; Blade Width: 20; Region Start: 1; Border: 1; Title Block Position: 3
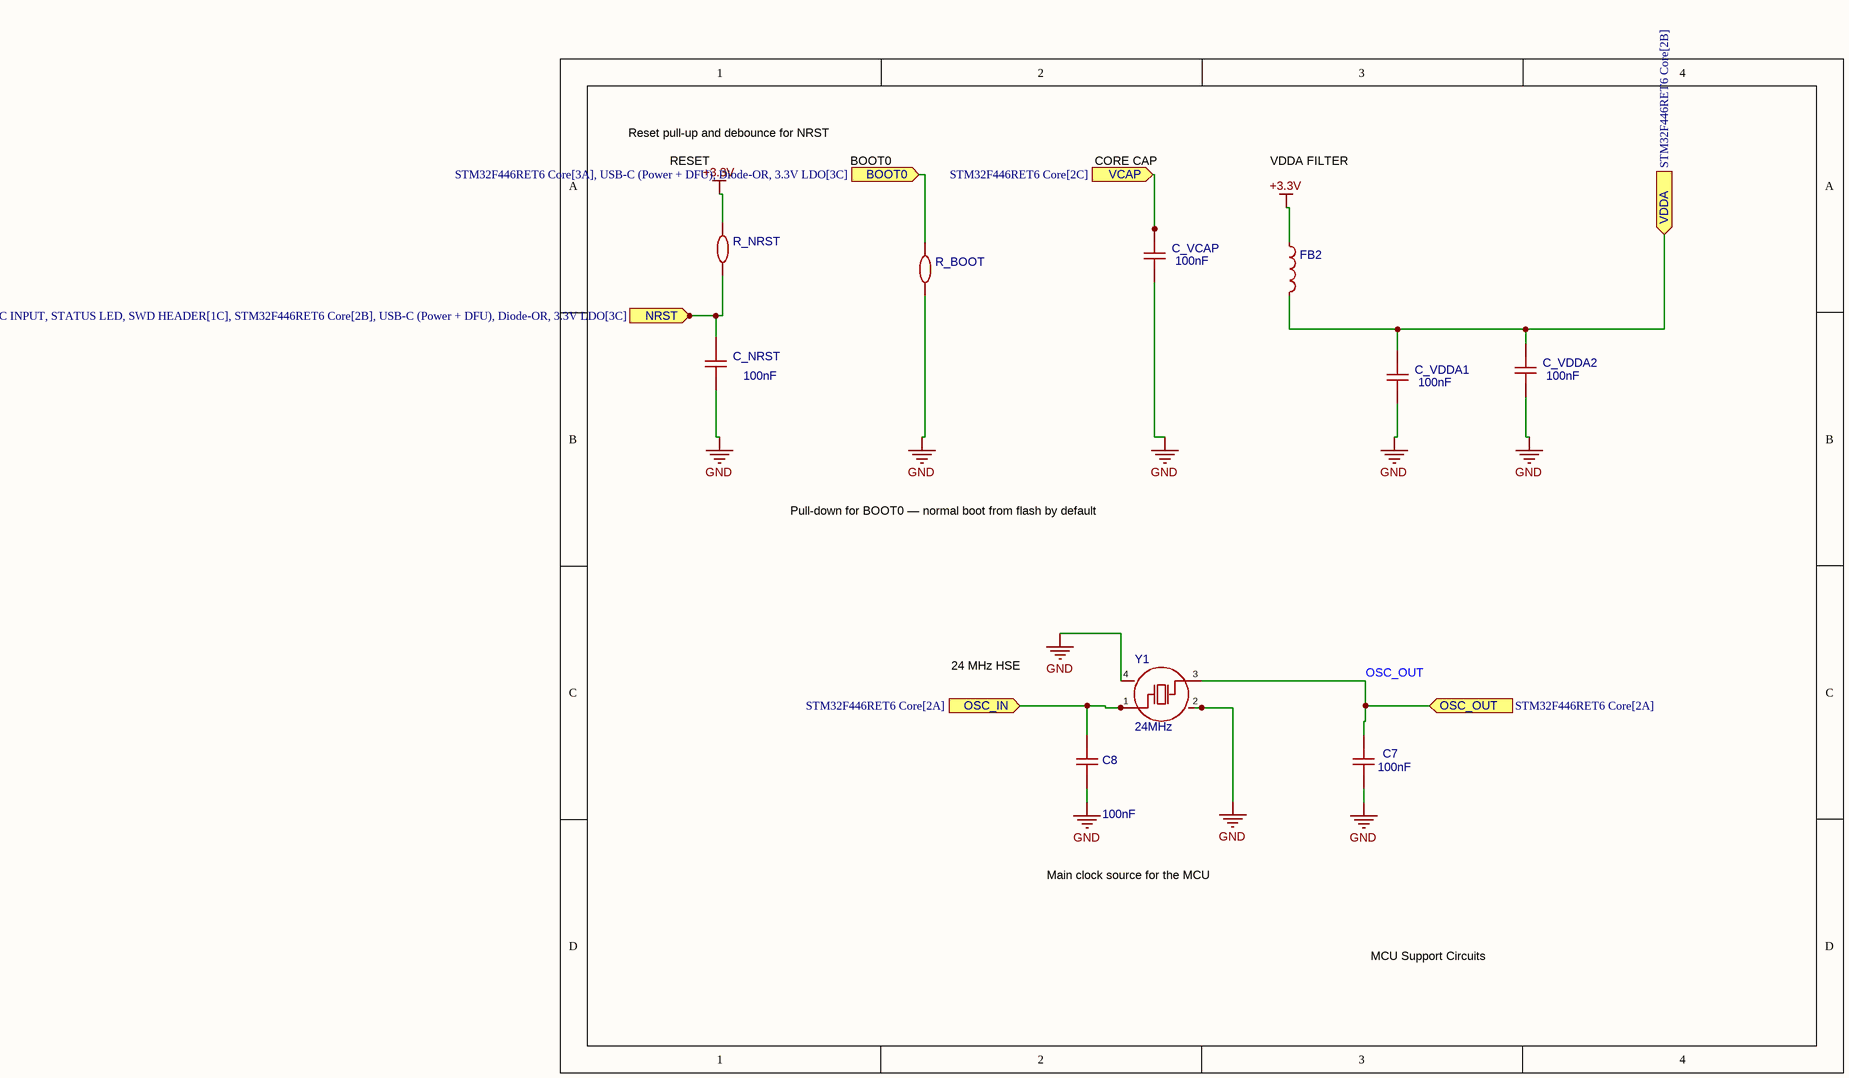
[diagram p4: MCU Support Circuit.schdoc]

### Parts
C7  100nF  [0603C]
C8  100nF  [0603C]
C_NRST  100nF  [0603C]
C_VCAP  100nF  [0603C]
C_VDDA1  100nF  [0603C]
C_VDDA2  100nF  [0603C]
FB2  BLM18AG121SN1D  [0603L]  (value not drawn)
R_BOOT  10kΩ  [0603R]  (value not drawn)
R_NRST  10kΩ  [0603R]  (value not drawn)
Y1  24MHz  [CRYSTAL-SMD_4P-L2.0-W1.6-BL-1]

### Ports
BOOT0 (in, see STM32F446RET6 Core[3A], USB-C (Power + DFU), Diode-OR, 3.3V LDO[3C]), NRST (in, see RC INPUT, STATUS LED, SWD HEADER[1C], STM32F446RET6 Core[2B], USB-C (Power + DFU), Diode-OR, 3.3V LDO[3C]), OSC_IN (in, see STM32F446RET6 Core[2A]), OSC_OUT (in, see STM32F446RET6 Core[2A]), VCAP (in, see STM32F446RET6 Core[2C]), VDDA (in, see STM32F446RET6 Core[2B])

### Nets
+3.3V: FB2.1 R_NRST.1
GND: C7.2 C8.2 C_NRST.2 C_VCAP.2 C_VDDA1.2 C_VDDA2.2 R_BOOT.2 Y1.2(NC) Y1.4(NC)
BOOT0: R_BOOT.1 ; port BOOT0
NRST: C_NRST.1 R_NRST.2 ; port NRST
OSC_IN: C8.1 Y1.1(OSC1) ; port OSC_IN
OSC_OUT: C7.1 Y1.3(OSC2) ; port OSC_OUT
VCAP: C_VCAP.1 ; port VCAP
NetC_VDDA1_1: C_VDDA1.1 C_VDDA2.1 FB2.2 ; port VDDA

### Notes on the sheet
- Reset pull-up and debounce for NRST
- RESET
- BOOT0
- CORE CAP
- VDDA FILTER
- Pull-down for BOOT0 — normal boot from flash by default
- 24 MHz HSE
- Main clock source for the MCU
- MCU Support Circuits

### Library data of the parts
C7 C8 C_NRST C_VCAP C_VDDA1 C_VDDA2 = CC0603KRX7R9BB104: Capacitance:100nF Tolerance:±10% Tolerance:±10% Voltage Rating:50V Temperature Coefficient:X7R; Manufacturer: YAGEO(国巨); Tolerance: ±10%; Voltage Rating: 50V; Add into BOM: yes; 3D Model: 624118aa3cc7497086c383c2d72e0852; 3D Model Transform: 62.992,31.496,0,0,0,0,0,0,0; Temperature Coefficient: X7R; ModelName: C0603_L1.6-W0.8-H0.8
FB2 = BLM18AG121SN1D: Impedance @ Frequency:120Ω@100MHz Tolerance:±25% Tolerance:±25% DC Resistance(DCR):180mΩ Current Rating:800mA Number of Circuits:1 Operating Temperature:-55℃~+125℃ Operating Temperature:-55℃~+125℃; Manufacturer: muRata(村田); Current Rating: 800mA; Tolerance: ±25%; Add into BOM: yes; 3D Model: ece81e7160a84e0c9a4133ba5d41d18a; 3D Model Transform: 62.992,31.496,0,180,0,0,0.094,0.629,0; DC Resistance(DCR): 180mΩ; Number of Circuits: 1; ModelName: L0603_L1.6-W0.8-H0.5_BEAD
R_BOOT R_NRST = RC0603JR-0710KL: Type:Thick Film Resistor Resistance:10kΩ Tolerance:±5% Tolerance:±5% Power(Watts):100mW Voltage-Supply(Max):75V Temperature Coefficient:±100ppm/℃ Temperature Coefficient:±100ppm/℃ Operating Temperature:-55℃~+155℃ Operating Temperature:-55℃~+155℃; Manufacturer: YAGEO(国巨); Tolerance: ±5%; Add into BOM: yes; 3D Model: 112863783b5b41f1b5254f87eedc7932; 3D Model Transform: 31.8897,63.7794,0,90,0,0,0,0,0; Power(Watts): 100mW; Voltage-Supply(Max): 75V; ModelName: R0603
Y1 = XRCGB24M000F3M00R0: Type:Crystal Oscillator Frequency:24MHz Normal temperature Frequency Tolerance:±30ppm Normal temperature Frequency Tolerance:±30ppm Load Capacitance:6pF Frequency Stability:±40ppm Frequency Stability:±40ppm Equivalent Series Resistance(ESR):150Ω Operating; Manufacturer: muRata(村田); Load Capacitance: 6pF; Frequency Stability: ±40ppm; Add into BOM: yes; 3D Model: 5de808a48c6e4dc7933aafd5de6f241f; 3D Model Transform: 79.1337,62.992,0,0,0,0,0,0,0; Normal temperature Frequency Tolerance: ±30ppm; Equivalent Series Resistance(ESR): 150Ω; ModelName: CRYSTAL-SMD_4P-L2.0-W1.6-BL-B

## Sheet RC INPUT, STATUS LED, SWD HEADER.schdoc
size 241 x 190 mm; Device: Altium_A; SheetNumber: 6; SheetTotal: 8; Name: Altium_A; Width: 950; Height: 750; X Region Count: 4; Y Region Count: 4; Blade Width: 20; Region Start: 1; Border: 1; Title Block Position: 3
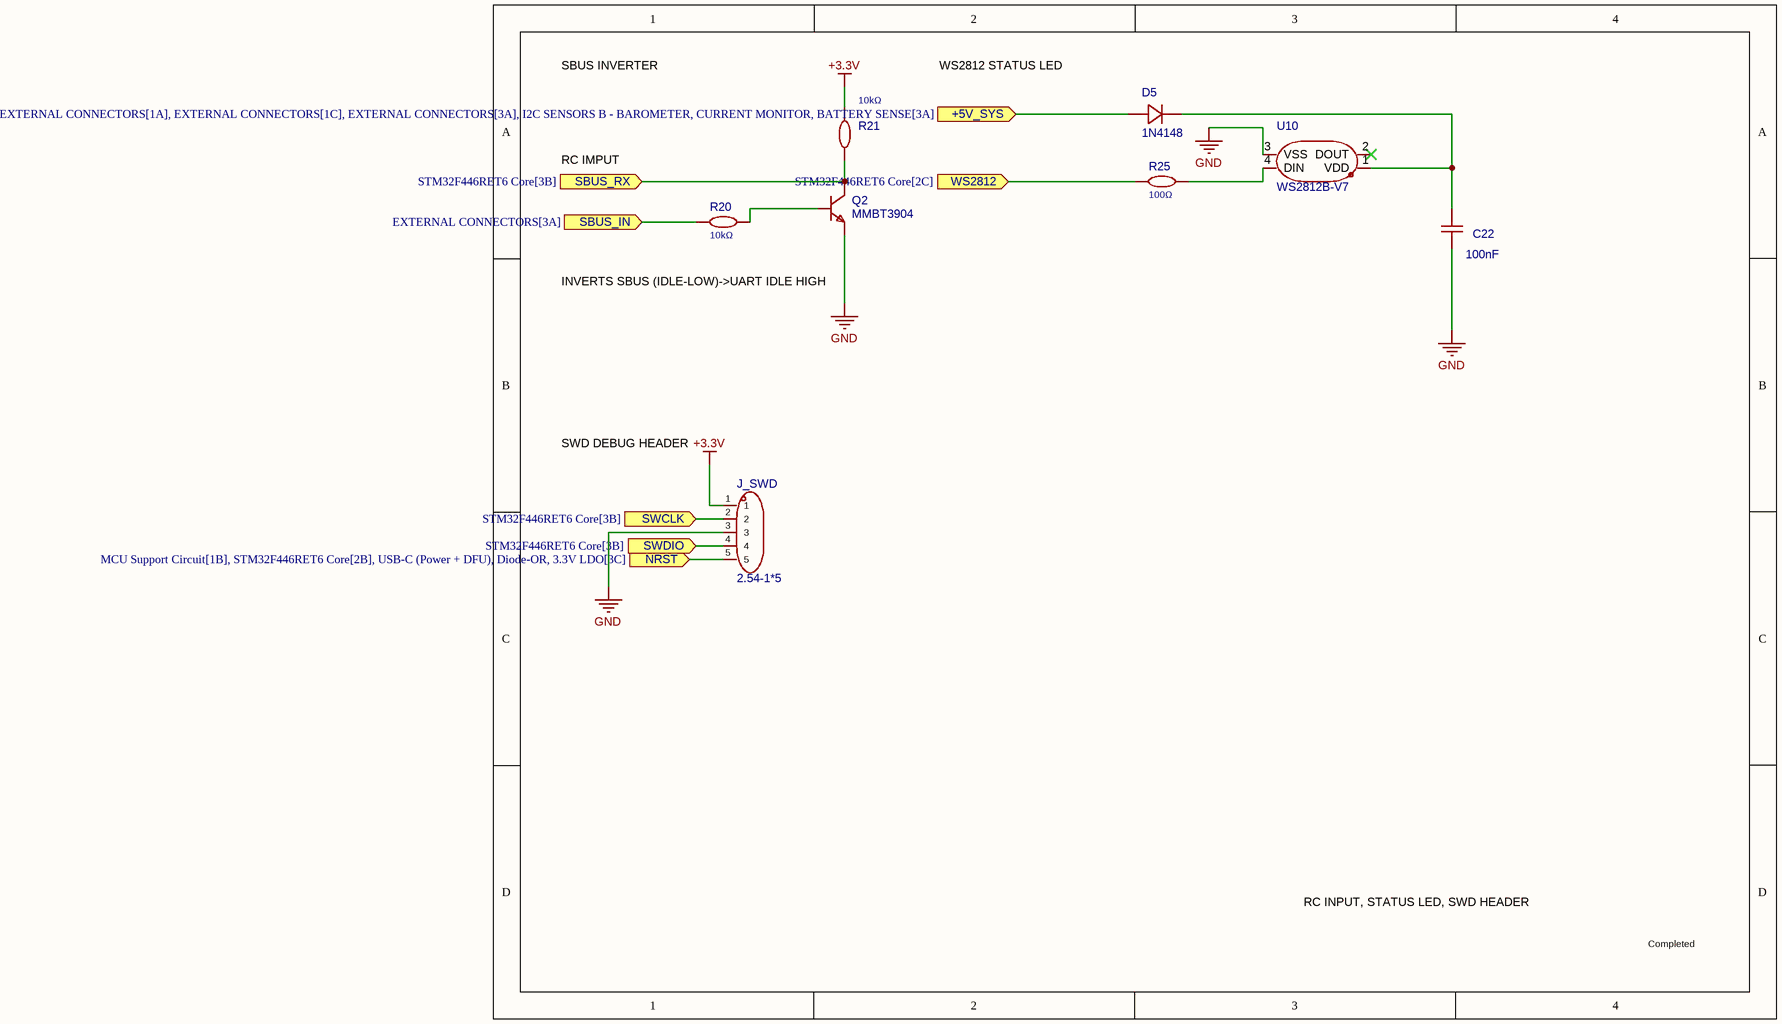
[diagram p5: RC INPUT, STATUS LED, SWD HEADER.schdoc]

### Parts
C22  100nF  [0603C]
D5  1N4148  [DO35-2_D2r00x4r20-H2r00-P7r62]
J_SWD  2.54-1*5  [ZX-XH2_54-5PZZ]
Q2  MMBT3904  [SOT23-3-1r90-2r90x1r30-H1r12]
R20  10kΩ  [0805R]
R21  10kΩ  [0805R]
R25  100Ω  [0603R]
U10  WS2812B-V7  [LED-SMD_5050WS2812B]

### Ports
+5V_SYS (in, see EXTERNAL CONNECTORS[1A], EXTERNAL CONNECTORS[1C], EXTERNAL CONNECTORS[3A], I2C SENSORS B - BAROMETER, CURRENT MONITOR, BATTERY SENSE[3A]), NRST (in, see MCU Support Circuit[1B], STM32F446RET6 Core[2B], USB-C (Power + DFU), Diode-OR, 3.3V LDO[3C]), SBUS_IN (in, see EXTERNAL CONNECTORS[3A]), SBUS_RX (in, see STM32F446RET6 Core[3B]), SWCLK (in, see STM32F446RET6 Core[3B]), SWDIO (in, see STM32F446RET6 Core[3B]), WS2812 (in, see STM32F446RET6 Core[2C])

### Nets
+3.3V: J_SWD.1 R21.1
GND: C22.2 J_SWD.3 Q2.2(E) U10.3(VSS)
+5V_SYS: D5.1(A) ; port +5V_SYS
NRST: J_SWD.5 ; port NRST
SBUS_IN: R20.2 ; port SBUS_IN
WS2812: R25.2 ; port WS2812
NetC22_1: C22.1 D5.2(C) U10.1(VDD)
NetJ_SWD_2: J_SWD.2 ; port SWCLK
NetJ_SWD_4: J_SWD.4 ; port SWDIO
NetQ2_1: Q2.1(B) R20.1
NetQ2_3: Q2.3(C) R21.2 ; port SBUS_RX
NetR25_1: R25.1 U10.4(DIN)

Not connected (* = marked no-connect by the designer): U10 2(DOUT)*

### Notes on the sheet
- SBUS INVERTER
- WS2812 STATUS LED
- RC IMPUT
- INVERTS SBUS (IDLE-LOW)->UART IDLE HIGH
- SWD DEBUG HEADER
- RC INPUT, STATUS LED, SWD HEADER
- Completed

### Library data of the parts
C22 = CT41G-0603-2X1-50V-0.1uF-K(N): as C2 on sheet Battery Input, Protection, 5.2V Buck
D5 = 1N4148_C18195411: Diode Configuration:1 Independent Pd - Power Dissipation:500mW Current - Rectified:150mA Voltage - DC Reverse(Vr):100V Voltage - Forward(Vf@If):1V@10mA Non-Repetitive Peak Forward Surge Current:500mA Reverse Leakage Current (Ir):5mA Reverse Recovery Time; Manufacturer: LJ(朗捷); Add into BOM: yes; 3D Model: 79363fa573524412b13d67f0347598ab; 3D Model Transform: 334.645,87.008,0,0,0,0,0,0,-196.85; Pd - Power Dissipation: 500mW; Current - Rectified: 150mA; Voltage - DC Reverse(Vr): 100V; Non-Repetitive Peak Forward Surge Current: 500mA; Reverse Leakage Current (Ir): 5mA; Reverse Recovery Time (trr): 4ns; Operating Junction Temperature Range: -60℃~+200℃; ModelName: DO-35_BD2.2-L4.0-D0.50_1N4148
J_SWD = 2.54-1*5: Pin Structure:1x5P Pitch:2.54mm Circluar Pins/Square Pins:Pin Header Mounting Type:Through Hole Number of Rows:1 Number of Pins:5P Current Rating:2.5A Length of Mating Pin:6mm Insulation Height:2.54mm Length of End Connection Pin:3mm Contact Material:Bras; Manufacturer: ZHOURI(洲日); Add into BOM: yes; 3D Model: 98c612b43cbb479a86eae3328ff22ecc; 3D Model Transform: 499.999,100,0,0,0,0,0,0,-118.11; Pin Structure: 1x5P; Pitch: 2.54mm; Current Rating: 2.5A; ModelName: HDR-TH_5P-P2.54-M-LI-1X5P
Q2 = MMBT3904_C51953474: type:NPN Current - Collector(Ic):200mA Collector - Emitter Voltage VCEO:40V Pd - Power Dissipation:200mW DC Current Gain:300 DC Current Gain:300 Transition frequency(fT):300MHz Current - Collector Cutoff:100nA Vce Saturation(VCE(sat)):300mV Operating Temp; Manufacturer: CCX(晁禾); Add into BOM: yes; 3D Model: 62a57c6760504a01965db6419a6d07df; 3D Model Transform: 98.425,114.173,0,180,0,0,0.0005,-0.0005,0; type: NPN; Current - Collector(Ic): 200mA; Collector - Emitter Voltage VCEO: 40V; Pd - Power Dissipation: 200mW; DC Current Gain: 300; Transition frequency(fT): 300MHz; Current - Collector Cutoff: 100nA; Vce Saturation(VCE(sat)): 300mV; Emitter-Base Voltage(Vebo): 6V; Number: 1 NPN; Configuration: Standalone; ModelName: SOT-23-3P_L2.9-W1.3-H1.0-LS2.4-P0.95
R20 R21 = 0805W8F1002T5E: as R3 on sheet Battery Input, Protection, 5.2V Buck
R25 = TD03G1000FT: Type:Thin Film Resistor Resistance:100Ω Tolerance:±1% Tolerance:±1% Power(Watts):100mW Voltage-Supply(Max):50V Temperature Coefficient:±25ppm/℃ Temperature Coefficient:±25ppm/℃ Operating Temperature:-55℃~+155℃ Operating Temperature:-55℃~+155℃; Manufacturer: FH(风华); Tolerance: ±1%; Add into BOM: yes; 3D Model: 112863783b5b41f1b5254f87eedc7932; 3D Model Transform: 31.8897,63.7794,0,90,0,0,0,0,0; Power(Watts): 100mW; Voltage-Supply(Max): 50V; ModelName: R0603
U10 = WS2812B-V7: Manufacturer: worldsemi; Add into BOM: yes; 3D Model: 81dc68f5f77f41c7904cc185c7ab8064; 3D Model Transform: 208.661,196.85,0,0,0,0,0,0,0

## Sheet STM32F446RET6 Core.schdoc
size 241 x 190 mm; Device: Altium_A; SheetNumber: 7; SheetTotal: 8; Name: Altium_A; Width: 950; Height: 750; X Region Count: 4; Y Region Count: 4; Blade Width: 20; Region Start: 1; Border: 1; Title Block Position: 3
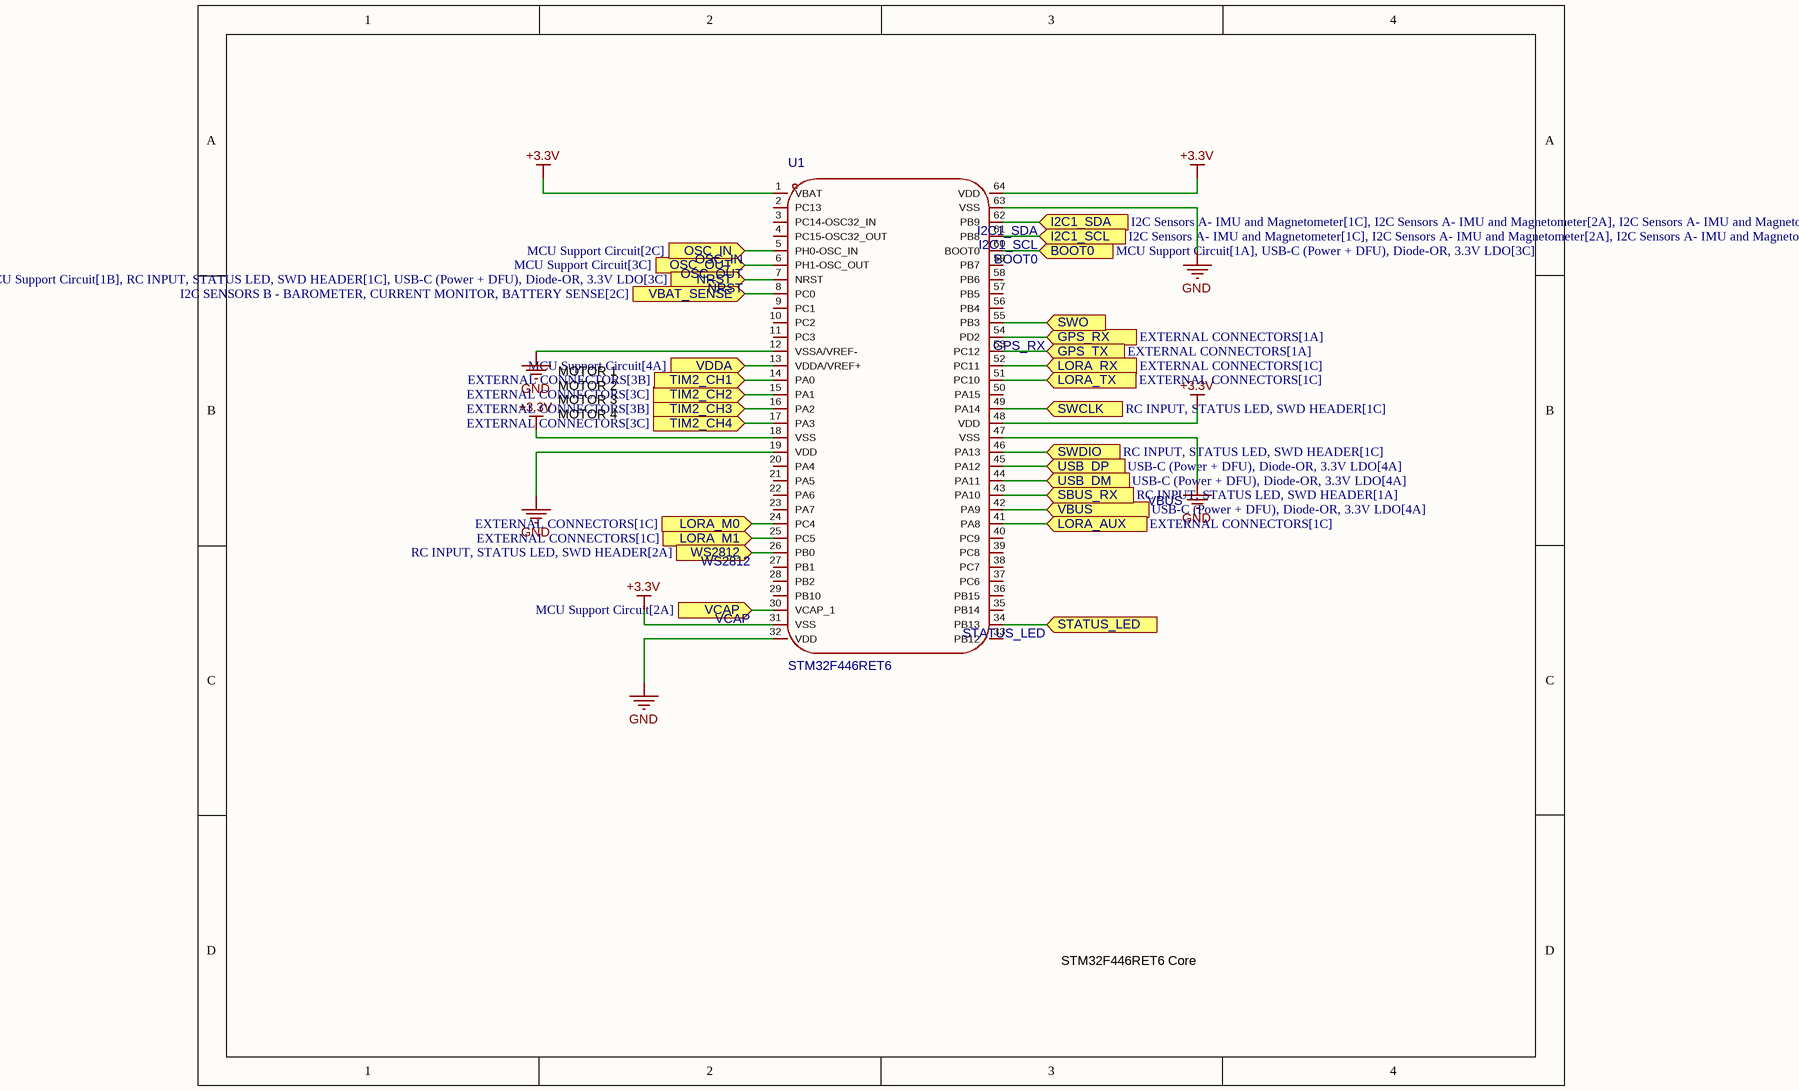
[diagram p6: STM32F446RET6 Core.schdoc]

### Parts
U1  STM32F446RET6  [LQFP-64_L10.0-W10.0-P0.50-LS12.0-BL]

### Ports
BOOT0 (in, see MCU Support Circuit[1A], USB-C (Power + DFU), Diode-OR, 3.3V LDO[3C]), GPS_RX (in, see EXTERNAL CONNECTORS[1A]), GPS_TX (in, see EXTERNAL CONNECTORS[1A]), I2C1_SCL (in, see I2C Sensors A- IMU and Magnetometer[1C], I2C Sensors A- IMU and Magnetometer[2A], I2C Sensors A- IMU and Magnetometer[3C], I2C SENSORS B - BAROMETER, CURRENT MONITOR, BATTERY SENSE[2B], I2C SENSORS B - BAROMETER, CURRENT MONITOR, BATTERY SENSE[4A]), I2C1_SDA (in, see I2C Sensors A- IMU and Magnetometer[1C], I2C Sensors A- IMU and Magnetometer[2A], I2C Sensors A- IMU and Magnetometer[3C], I2C SENSORS B - BAROMETER, CURRENT MONITOR, BATTERY SENSE[2A], I2C SENSORS B - BAROMETER, CURRENT MONITOR, BATTERY SENSE[4A]), LORA_AUX (in, see EXTERNAL CONNECTORS[1C]), LORA_M0 (in, see EXTERNAL CONNECTORS[1C]), LORA_M1 (in, see EXTERNAL CONNECTORS[1C]), LORA_RX (in, see EXTERNAL CONNECTORS[1C]), LORA_TX (in, see EXTERNAL CONNECTORS[1C]), NRST (in, see MCU Support Circuit[1B], RC INPUT, STATUS LED, SWD HEADER[1C], USB-C (Power + DFU), Diode-OR, 3.3V LDO[3C]), OSC_IN (in, see MCU Support Circuit[2C]), OSC_OUT (in, see MCU Support Circuit[3C]), SBUS_RX (in, see RC INPUT, STATUS LED, SWD HEADER[1A]), STATUS_LED (in), SWCLK (in, see RC INPUT, STATUS LED, SWD HEADER[1C]), SWDIO (in, see RC INPUT, STATUS LED, SWD HEADER[1C]), SWO (in), TIM2_CH1 (in, see EXTERNAL CONNECTORS[3B]), TIM2_CH2 (in, see EXTERNAL CONNECTORS[3C]), TIM2_CH3 (in, see EXTERNAL CONNECTORS[3B]), TIM2_CH4 (in, see EXTERNAL CONNECTORS[3C]), USB_DM (in, see USB-C (Power + DFU), Diode-OR, 3.3V LDO[4A]), USB_DP (in, see USB-C (Power + DFU), Diode-OR, 3.3V LDO[4A]), VBAT_SENSE (in, see I2C SENSORS B - BAROMETER, CURRENT MONITOR, BATTERY SENSE[2C]), VBUS (in, see USB-C (Power + DFU), Diode-OR, 3.3V LDO[4A]), VCAP (in, see MCU Support Circuit[2A]), VDDA (in, see MCU Support Circuit[4A]), WS2812 (in, see RC INPUT, STATUS LED, SWD HEADER[2A])

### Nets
+3.3V: U1.1(VBAT) U1.18(VSS) U1.31(VSS) U1.48(VDD) U1.64(VDD)
GND: U1.12(VSSA/VREF-) U1.19(VDD) U1.32(VDD) U1.47(VSS) U1.63(VSS)
BOOT0: U1.60(BOOT0) ; port BOOT0
GPS_RX: U1.54(PD2) ; port GPS_RX
GPS_TX: U1.53(PC12) ; port GPS_TX
I2C1_SCL: U1.61(PB8) ; port I2C1_SCL
I2C1_SDA: U1.62(PB9) ; port I2C1_SDA
LORA_AUX: U1.41(PA8) ; port LORA_AUX
LORA_M0: U1.24(PC4) ; port LORA_M0
LORA_M1: U1.25(PC5) ; port LORA_M1
LORA_RX: U1.52(PC11) ; port LORA_RX
LORA_TX: U1.51(PC10) ; port LORA_TX
NRST: U1.7(NRST) ; port NRST
OSC_IN: U1.5(PH0-OSC_IN) ; port OSC_IN
OSC_OUT: U1.6(PH1-OSC_OUT) ; port OSC_OUT
STATUS_LED: U1.34(PB13) ; port STATUS_LED
TIM2_CH1: U1.14(PA0) ; port TIM2_CH1
TIM2_CH2: U1.15(PA1) ; port TIM2_CH2
TIM2_CH3: U1.16(PA2) ; port TIM2_CH3
TIM2_CH4: U1.17(PA3) ; port TIM2_CH4
USB_DM: U1.44(PA11) ; port USB_DM
VBAT_SENSE: U1.8(PC0) ; port VBAT_SENSE
VBUS: U1.42(PA9) ; port VBUS
VCAP: U1.30(VCAP_1) ; port VCAP
WS2812: U1.26(PB0) ; port WS2812
NetC_VDDA1_1: U1.13(VDDA/VREF+) ; port VDDA
NetJ_SWD_2: U1.49(PA14) ; port SWCLK
NetJ_SWD_4: U1.46(PA13) ; port SWDIO
NetQ2_3: U1.43(PA10) ; port SBUS_RX
NetU1_45: U1.45(PA12) ; port USB_DP
NetU1_55: U1.55(PB3) ; port SWO

Not connected (* = marked no-connect by the designer): U1 2(PC13) 3(PC14-OSC32_IN) 4(PC15-OSC32_OUT) 9(PC1) 10(PC2) 11(PC3) 20(PA4) 21(PA5) 22(PA6) 23(PA7) 27(PB1) 28(PB2) 29(PB10) 33(PB12) 35(PB14) 36(PB15) 37(PC6) 38(PC7) 39(PC8) 40(PC9) 50(PA15) 56(PB4) 57(PB5) 58(PB6) 59(PB7)

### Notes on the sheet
- MOTOR 2
- MOTOR 1
- MOTOR 4
- MOTOR 3
- STM32F446RET6 Core
- Labels drawn without touching a wire or pin: VBUS

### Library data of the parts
U1 = STM32F446RET6: CPU Core:ARM Cortex-M4 CPU Maximum Speed:180MHz Core Size:32 Bit Program Storage Size:512KB Program Memory Type:FLASH RAM Size:128KB EEPROM:- Number of I/O:50 ADC (Bit):12bit DAC (Bit):12bit Oscillator Type:Built-in Voltage - Supply:1.7V~3.6V Voltage - Su; Manufacturer: ST(意法半导体); Add into BOM: yes; 3D Model: 9827011a374c44f2b05ac1eacaf21ae0; 3D Model Transform: 472.441,472.441,0,0,0,0,0,0.465,0; CPU Maximum Speed: 180MHz; Core Size: 32 Bit; Program Storage Size: 512KB; Program Memory Type: FLASH; RAM Size: 128KB; Number of I/O: 50; ADC (Bit): 12bit; ModelName: LQFP-64_L10.0-W10.0-H1.4-LS12.0-P0.50

## Sheet USB-C (Power + DFU), Diode-OR, 3.3V LDO.schdoc
size 241 x 190 mm; Device: Altium_A; SheetNumber: 8; SheetTotal: 8; Name: Altium_A; Width: 950; Height: 750; X Region Count: 4; Y Region Count: 4; Blade Width: 20; Region Start: 1; Border: 1; Title Block Position: 3
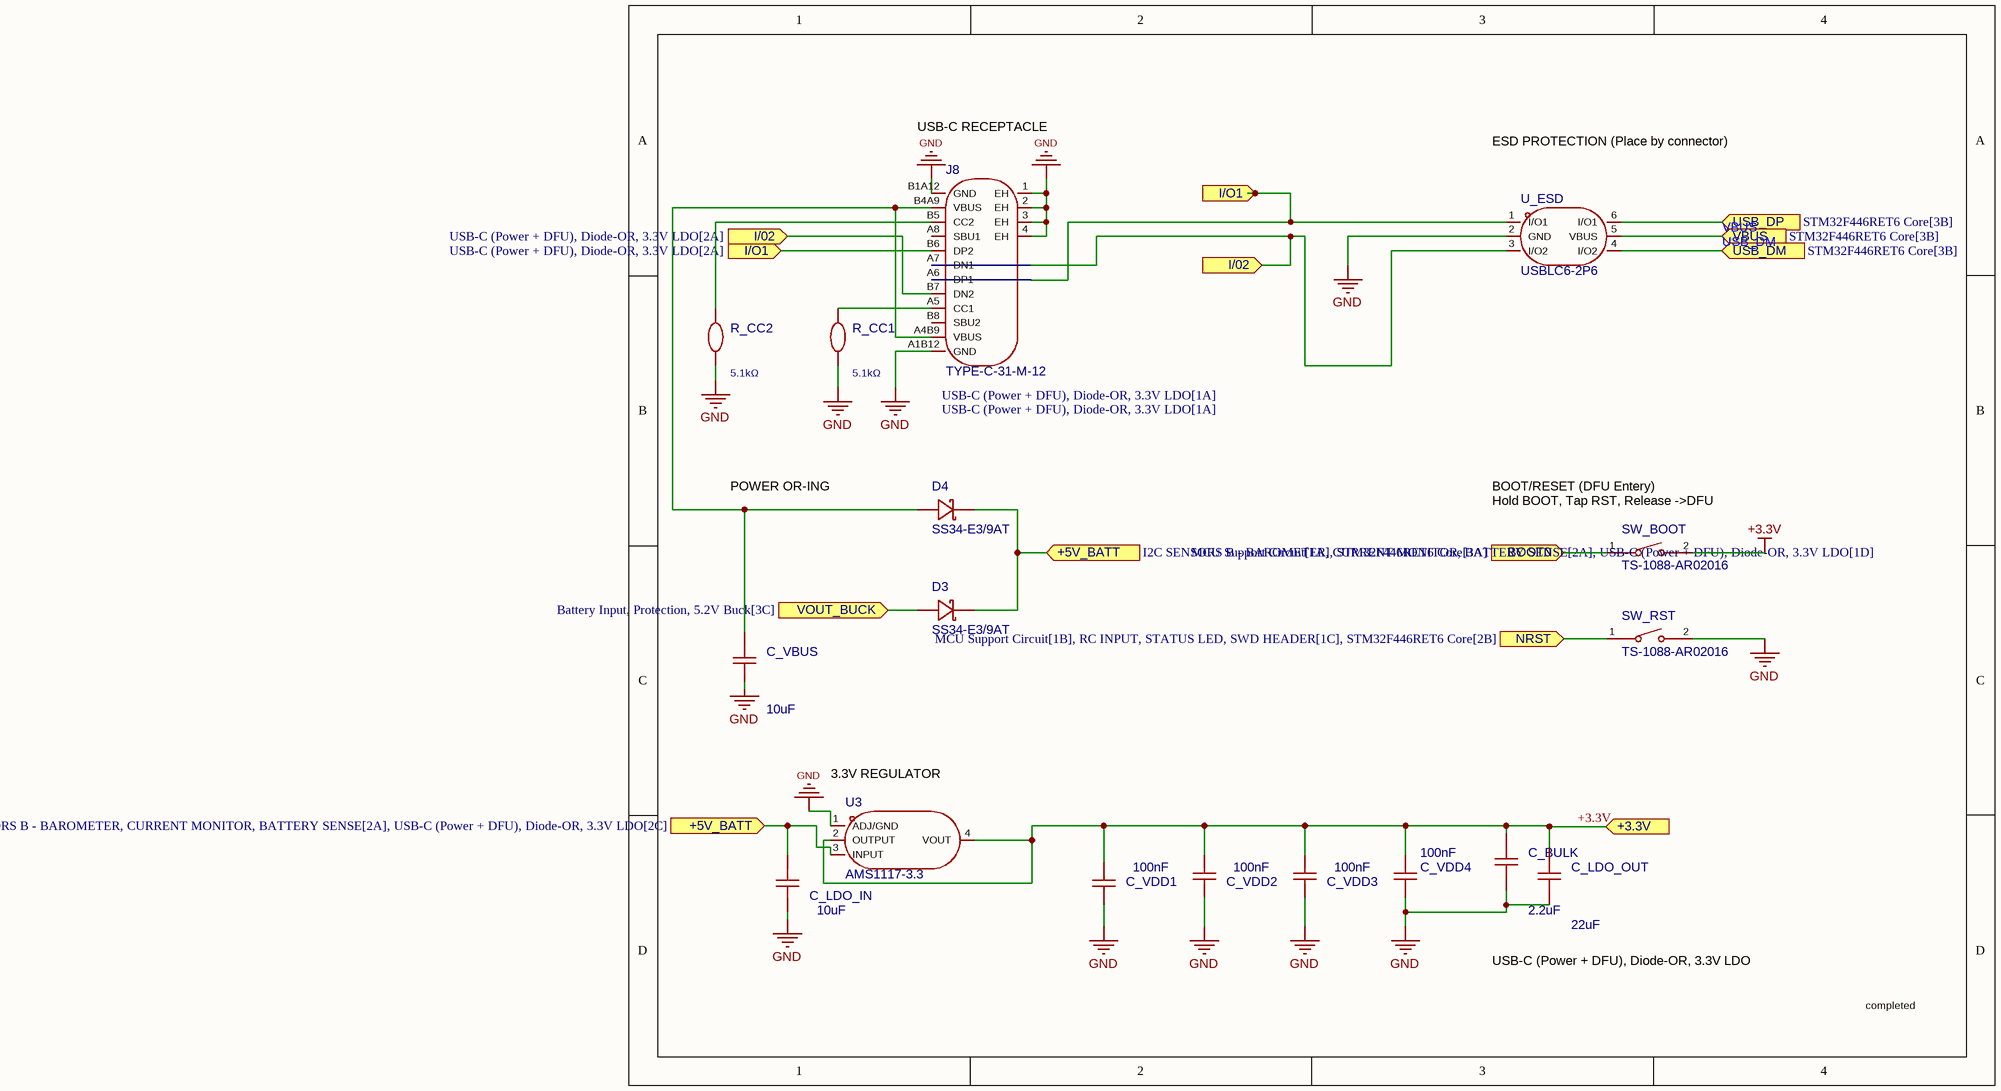
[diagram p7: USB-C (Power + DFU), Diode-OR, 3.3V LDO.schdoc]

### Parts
C_BULK  2.2uF  [0603C]
C_LDO_IN  10uF  [0603C]
C_LDO_OUT  22uF  [0603C]
C_VBUS  10uF  [0603C]
C_VDD1  100nF  [0603C]
C_VDD2  100nF  [0603C]
C_VDD3  100nF  [0603C]
C_VDD4  100nF  [0603C]
D3  SS34-E3/9AT  [SMC-2_7r94x5r91-H2r34_C]
D4  SS34-E3/9AT  [SMC-2_7r94x5r91-H2r34_C]
J8  TYPE-C-31-M-12  [USB-C_SMD-TYPE-C-31-M-12]
R_CC1  5.1kΩ  [0603R]
R_CC2  5.1kΩ  [0603R]
SW_BOOT  TS-1088-AR02016  [SW-SMD_L3.9-W3.0-P4.45]
SW_RST  TS-1088-AR02016  [SW-SMD_L3.9-W3.0-P4.45]
U3  AMS1117-3.3  [SOT-223-3_L6.5-W3.4-P2.30-LS7.0-BR]
U_ESD  USBLC6-2P6  [SOT563-6_1r60x1r20-H0r55-P0r50]

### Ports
+3.3V (in), +5V_BATT (in, see I2C SENSORS B - BAROMETER, CURRENT MONITOR, BATTERY SENSE[2A], USB-C (Power + DFU), Diode-OR, 3.3V LDO[1D]), +5V_BATT (in, see I2C SENSORS B - BAROMETER, CURRENT MONITOR, BATTERY SENSE[2A], USB-C (Power + DFU), Diode-OR, 3.3V LDO[2C]), BOOT0 (in, see MCU Support Circuit[1A], STM32F446RET6 Core[3A]), I/02 (in, see USB-C (Power + DFU), Diode-OR, 3.3V LDO[1A]), I/02 (in, see USB-C (Power + DFU), Diode-OR, 3.3V LDO[2A]), I/O1 (in, see USB-C (Power + DFU), Diode-OR, 3.3V LDO[1A]), I/O1 (in, see USB-C (Power + DFU), Diode-OR, 3.3V LDO[2A]), NRST (in, see MCU Support Circuit[1B], RC INPUT, STATUS LED, SWD HEADER[1C], STM32F446RET6 Core[2B]), USB_DM (in, see STM32F446RET6 Core[3B]), USB_DP (in, see STM32F446RET6 Core[3B]), VBUS (in, see STM32F446RET6 Core[3B]), VOUT_BUCK (in, see Battery Input, Protection, 5.2V Buck[3C])

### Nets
+3.3V: C_BULK.1 C_LDO_OUT.1 C_VDD1.1 C_VDD2.1 C_VDD3.1 C_VDD4.1 SW_BOOT.2 U3.2(OUTPUT) U3.4(VOUT) ; port +3.3V
GND: C_BULK.2 C_LDO_IN.2 C_LDO_OUT.2 C_VBUS.2 C_VDD1.2 C_VDD2.2 C_VDD3.2 C_VDD4.2 J8.1(EH) J8.2(EH) J8.3(EH) J8.4(EH) J8.A1B12(GND) J8.B1A12(GND) R_CC1.2 R_CC2.2 SW_RST.2 U3.1(ADJ/GND) U_ESD.2(GND)
BOOT0: SW_BOOT.1 ; port BOOT0
NRST: SW_RST.1 ; port NRST
USB_DM: U_ESD.4(I/O2) ; port USB_DM
VBUS: U_ESD.5(VBUS) ; port VBUS
NetC5_1: D3.2(A) ; port VOUT_BUCK
NetC_LDO_IN_1: C_LDO_IN.1 D3.1(K) D4.1(K) U3.3(INPUT) ; port +5V_BATT
NetC_VBUS_1: C_VBUS.1 D4.2(A) J8.A4B9(VBUS) J8.B4A9(VBUS)
NetJ8_A5: J8.A5(CC1) R_CC1.1
NetJ8_A6: J8.A6(DP1) J8.B6(DP2) U_ESD.1(I/O1) ; port I/O1
NetJ8_A7: J8.A7(DN1) J8.B7(DN2) U_ESD.3(I/O2) ; port I/02
NetJ8_B5: J8.B5(CC2) R_CC2.1
NetU1_45: U_ESD.6(I/O1) ; port USB_DP

Not connected (* = marked no-connect by the designer): J8 A8(SBU1) B8(SBU2)

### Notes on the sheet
- USB-C RECEPTACLE
- ESD PROTECTION (Place by connector)
- POWER OR-ING
- BOOT/RESET (DFU Entery)
- (near SW_BOOT) Hold BOOT, Tap RST, Release ->DFU
- (near U3) 3.3V REGULATOR
- USB-C (Power + DFU), Diode-OR, 3.3V LDO
- completed

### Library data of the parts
C_BULK = 0603X225M160NT: Capacitance:2.2uF Tolerance:±20% Tolerance:±20% Voltage Rating:16V; Manufacturer: FH(风华); Tolerance: ±20%; Voltage Rating: 16V; Add into BOM: yes; 3D Model: 624118aa3cc7497086c383c2d72e0852; 3D Model Transform: 62.992,31.496,0,0,0,0,0,0,0; ModelName: C0603_L1.6-W0.8-H0.8
C_LDO_IN C_VBUS = 0603X106M250NT: as C3 on sheet Battery Input, Protection, 5.2V Buck
C_LDO_OUT = FCC0603X226M160CT: Capacitance:22uF Tolerance:±20% Tolerance:±20% Voltage Rating:16V Temperature Coefficient:X5R Operating Temperature:-55℃~+85℃ Operating Temperature:-55℃~+85℃; Manufacturer: FOJAN(富捷); Tolerance: ±20%; Voltage Rating: 16V; Add into BOM: yes; 3D Model: 624118aa3cc7497086c383c2d72e0852; 3D Model Transform: 62.992,31.496,0,0,0,0,0,0,0; Temperature Coefficient: X5R; ModelName: C0603_L1.6-W0.8-H0.8
C_VDD1-C_VDD4 = CT41G-0603-2X1-50V-0.1uF-K(N): as C_REGOUT on sheet I2C Sensors A- IMU and Magnetometer
D3 D4 = SS34-E3/9AT: as D2 on sheet Battery Input, Protection, 5.2V Buck
J8 = TYPE-C-31-M-12: Connector Type:Type-C Protocol Standard:- Gender:Female Mounting Type:Surface Mount, Right Angle Number of Contacts:16P Number of Ports:1 Current Rating-Power:5A Voltage Rating:20V Connect-Disconnect Life:10,000 cycles Length:7.35mm Operating Temperature:; Manufacturer: 韩国韩荣; Add into BOM: yes; 3D Model: 8421221a464047838322348b3a9debc3; 3D Model Transform: 351.9678,311.023,0,180,0,0,0,-43.307,-33.465; Connector Type: Type-C; Gender: Female; Number of Contacts: 16P; Number of Ports: 1; Current Rating-Power: 5A; Voltage Rating: 20V; ModelName: USB-C_SMD-TYPE-C-31-M-12_1
R_CC1 R_CC2 = FRC0603J512 TS: Type:Thick Film Resistor Resistance:5.1kΩ Tolerance:±5% Tolerance:±5% Power(Watts):100mW Voltage-Supply(Max):75V Temperature Coefficient:±100ppm/℃ Temperature Coefficient:±100ppm/℃ Operating Temperature:-55℃~+155℃ Operating Temperature:-55℃~+155℃; Manufacturer: FOJAN(富捷); Add into BOM: yes; Tolerance: ±5%; 3D Model: 112863783b5b41f1b5254f87eedc7932; 3D Model Transform: 31.8897,63.7794,0,90,0,0,0,0,0; Power(Watts): 100mW; Voltage-Supply(Max): 75V; ModelName: R0603
SW_BOOT = TS-1088-AR02016: Circuit:SPST Actuator Style:Round Button Operating Force:1.6N Mounting Type:Surface Mount,Vertical Length:3.9mm Width:3mm Switch Height:2mm with Bracket:Without Bracket Contact Current:50mA Voltage Rating:12V Actuator/Cap Color:Black With Lamp:- IP Rating; Manufacturer: XUNPU(讯普); Add into BOM: yes; Voltage Rating: 12V; 3D Model: 305d1c5953df46c2be38ec48c2aa1876; 3D Model Transform: 188.976,114.174,0,0,0,0,0,0,0; Circuit: SPST; Contact Current: 50mA; Actuator/Cap Color: Black; Operating Force: 1.6N; Life: 100,000 cycles; Switch Height: 2mm; ModelName: SW-SMD_L3.9-W2.9-H2.0-LS4.8
SW_RST = TS-1088-AR02016: Circuit:SPST Actuator Style:Round Button Operating Force:1.6N Mounting Type:Surface Mount,Vertical Length:3.9mm Width:3mm Switch Height:2mm with Bracket:Without Bracket Contact Current:50mA Voltage Rating:12V Actuator/Cap Color:Black With Lamp:- IP Rating; Manufacturer: XUNPU(讯普); Add into BOM: yes; Voltage Rating: 12V; 3D Model: 305d1c5953df46c2be38ec48c2aa1876; 3D Model Transform: 188.976,114.174,0,0,0,0,0,0,0; Circuit: SPST; Operating Force: 1.6N; Switch Height: 2mm; Contact Current: 50mA; Actuator/Cap Color: Black; Life: 100,000 cycles; ModelName: SW-SMD_L3.9-W2.9-H2.0-LS4.8
U3 = AMS1117-3.3_C18212698: Output Configuration:Positive Voltage - Supply:12V Output Voltage:3.3V Output Voltage:3.3V Output Current:1A Power Supply Rejection Ratio (PSRR):- Voltage Dropout:1.3V@(1A) standby current:4mA Noise:- Features:Over Current Protection；Thermal shutdown Oper; Manufacturer: TECH PUBLIC(台舟); Output Type: Fixed; Output Voltage: 3.3V; Add into BOM: yes; 3D Model: e5f8b32b785646b6abbef6d5ae2fe060; 3D Model Transform: 279.89794,255.905,0,180,0,0,-3.9385,-0.0005,0; Voltage - Supply: 12V; standby current: 4mA; Number of Outputs: 1; ModelName: SOT-223-4P_L6.5-W3.5-H1.6-LS7.0-P2.30
U_ESD = USBLC6-2P6_C49451919: Polarity:Unidirectional Reverse Stand-Off Voltage (Vrwm):5V Clamping Voltage:14V Peak Pulse Current (Ipp):5.5A Peak Pulse Power Dissipation (Ppp):80W Voltage - Breakdown:6V Reverse Leakage Current (Ir):80nA Number of Channels:2 Operating Temperature:-55℃~; Manufacturer: R+O(宏嘉诚); Add into BOM: yes; 3D Model: 13cd57c00ed845968c88bf9c0a30f0d4; 3D Model Transform: 62.992,62.992,0,90,0,0,-0.005,0.005,0; Reverse Stand-Off Voltage (Vrwm): 5V; Clamping Voltage: 14V; Peak Pulse Current (Ipp): 5.5A; Peak Pulse Power Dissipation (Ppp): 80W; Voltage - Breakdown: 6V; Reverse Leakage Current (Ir): 80nA; Number of Channels: 2; level of protection: IEC 61000-4-5；IEC 61000-4-2; Junction Capacitance: 0.5pF; ModelName: SOT-563-6P_L1.6-W1.2-H0.6-LS1.6-P0.50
